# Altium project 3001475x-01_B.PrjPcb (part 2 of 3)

## Sheet 06 - Gigabit Ethernet, Mini PCIe, microSIM.SchDoc: Gigabit, Ethernet, Mini PCIe, MicroSIM
size A3; PageSetup: Record=PageOptions|CenterHorizontal=True|CenterVertical=True|PrintScale=0.70|XCorrection=1.00|YCorrection=1.00|PrintKind=0|BorderSize=5000000|LeftOffset=0|BottomOffset=0|Orientation=2|PaperLength=4200|PaperWidth=2970|Scale=100|PaperSource=7|PrintQuality=600|MediaType=1|DitherType=10|PaperKind=A4|PrintScaleMode=1; Author: Daniel Alesanco; SheetNumber: 6; SheetTotal: 13
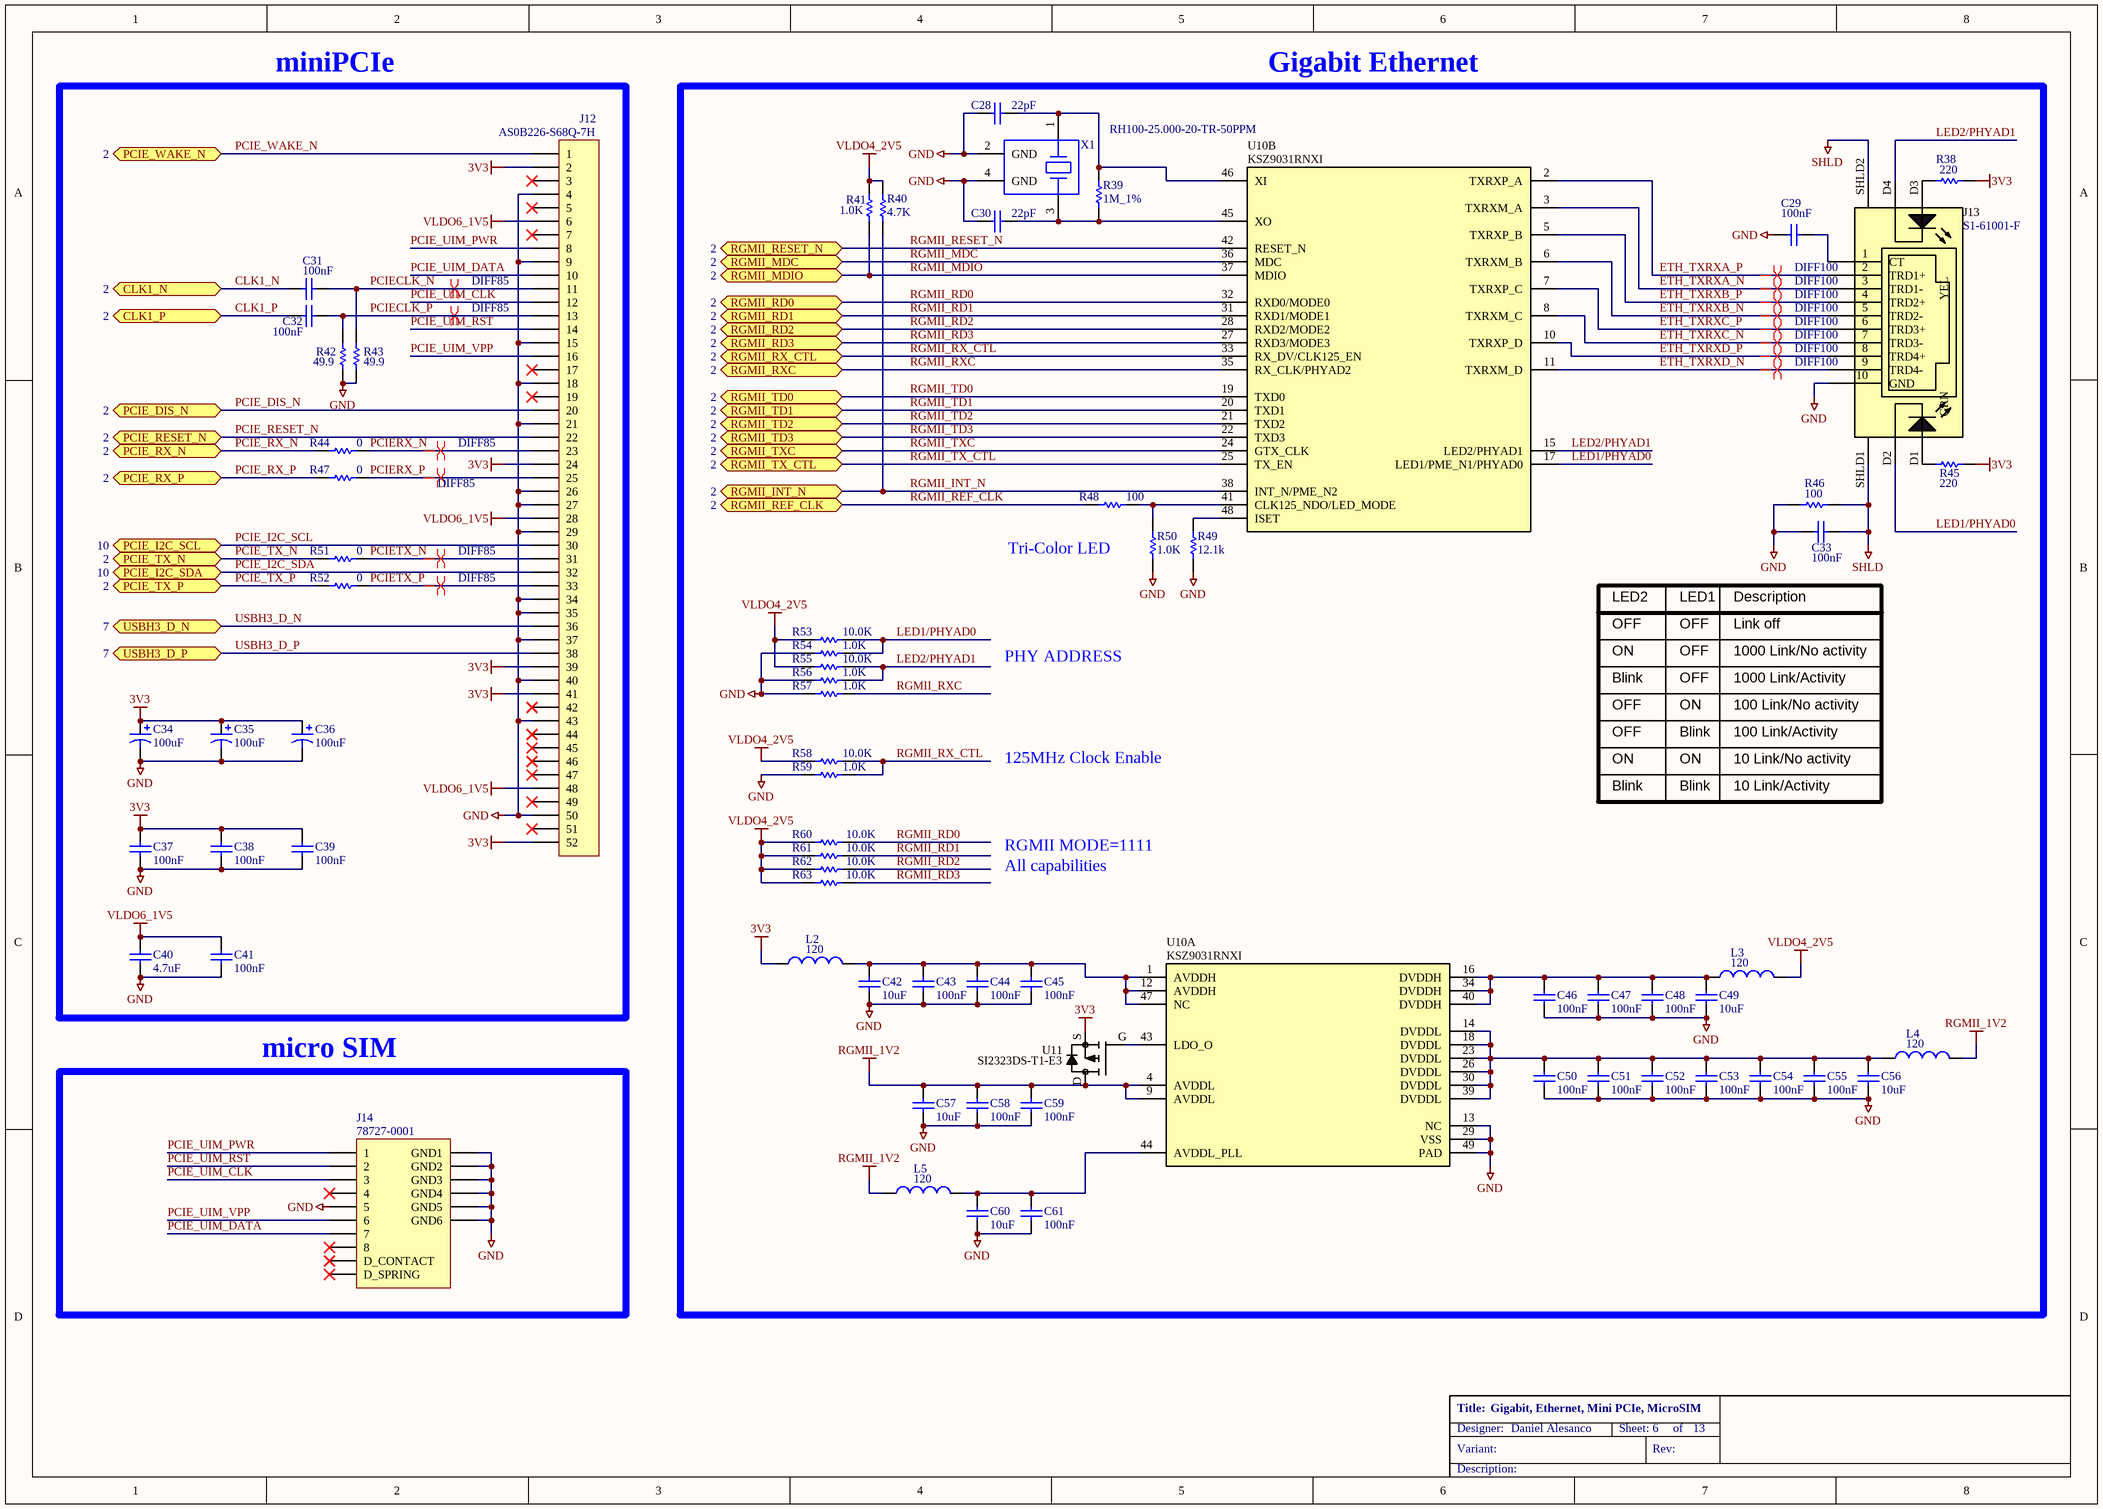
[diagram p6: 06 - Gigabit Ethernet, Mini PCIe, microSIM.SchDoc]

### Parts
C28  22pF  [CAPC1005X55N]
C29  100nF  [CAPC1005X55N]
C30  22pF  [CAPC1005X55N]
C31  100nF  [CAPC1005X55N]
C32  100nF  [CAPC1005X55N]
C33  100nF  [CAPC1005X55N]
C34  100uF  [CAPMP3216X120N]
C35  100uF  [CAPMP3216X120N]
C36  100uF  [CAPMP3216X120N]
C37  100nF  [CAPC1005X55N]
C38  100nF  [CAPC1005X55N]
C39  100nF  [CAPC1005X55N]
C40  4.7uF  [CAPC2013X135N]
C41  100nF  [CAPC1005X55N]
C42  10uF  [CAPC1005X55N]
C43  100nF  [CAPC1005X55N]
C44  100nF  [CAPC1005X55N]
C45  100nF  [CAPC1005X55N]
C46  100nF  [CAPC1005X55N]
C47  100nF  [CAPC1005X55N]
C48  100nF  [CAPC1005X55N]
C49  10uF  [CAPC1005X55N]
C50  100nF  [CAPC1005X55N]
C51  100nF  [CAPC1005X55N]
C52  100nF  [CAPC1005X55N]
C53  100nF  [CAPC1005X55N]
C54  100nF  [CAPC1005X55N]
C55  100nF  [CAPC1005X55N]
C56  10uF  [CAPC1005X55N]
C57  10uF  [CAPC1005X55N]
C58  100nF  [CAPC1005X55N]
C59  100nF  [CAPC1005X55N]
C60  10uF  [CAPC1005X55N]
C61  100nF  [CAPC1005X55N]
J12  Manufacturer_Part_Number: AS0B226-S68Q-7H  [FOXCONN_AS0B221-S68Q-7H]  (hidden comment: PCIe Minicard)
J13  Manufacturer_Part_Number: S1-61001-F  [BELFUSE_61001-F]  (hidden comment: RJ45)
J14  78727-0001  [MOLEX_78727-0001]
L2  120  [INDC1005X60N]
L3  120  [INDC1005X60N]
L4  120  [INDC1005X60N]
L5  120  [INDC1005X60N]
R38  220  [RESC1005X40N]
R39  1M_1%  [RESC1005X40N]
R40  4.7K  [RESC1005X40N]
R41  1.0K  [RESC1005X40N]
R42  49.9  [RESC1005X40N]
R43  49.9  [RESC1005X40N]
R44  0  [RESC1005X40N]
R45  220  [RESC1005X40N]
R46  100  [RESC1005X40N]
R47  0  [RESC1005X40N]
R48  100  [RESC1005X40N]
R49  12.1k  [RESC1005X40N]
R50  1.0K  [RESC1005X40N]
R51  0  [RESC1005X40N]
R52  0  [RESC1005X40N]
R53  10.0K  [RESC1005X40N]
R54  1.0K  [RESC1005X40N]
R55  10.0K  [RESC1005X40N]
R56  1.0K  [RESC1005X40N]
R57  1.0K  [RESC1005X40N]
R58  10.0K  [RESC1005X40N]
R59  1.0K  [RESC1005X40N]
R60  10.0K  [RESC1005X40N]
R61  10.0K  [RESC1005X40N]
R62  10.0K  [RESC1005X40N]
R63  10.0K  [RESC1005X40N]
U10  KSZ9031RNXI  [QFN50P700X700X100-49N]  (parts A,B of 2)
U11  SI2323DS-T1-E3  [SOT95P240X110_GSD-3N]
X1  RH100-25.000-20-TR-50PPM  [OSC210P320X250X90-4N]

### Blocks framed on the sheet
miniPCIe: C31 C32 C34-C41 J12 R42-R44 R47 R51 R52
Gigabit Ethernet: C28-C30 C33 C42-C61 J13 L2-L5 R38-R41 R45 R46 R48-R50 R53-R63 U10 U11 X1
micro SIM: J14

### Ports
CLK1_N (bidir, see 2), CLK1_P (bidir, see 2), PCIE_DIS_N (bidir, see 2), PCIE_I2C_SCL (bidir, see 10), PCIE_I2C_SDA (bidir, see 10), PCIE_RESET_N (bidir, see 2), PCIE_RX_N (bidir, see 2), PCIE_RX_P (bidir, see 2), PCIE_TX_N (bidir, see 2), PCIE_TX_P (bidir, see 2), PCIE_WAKE_N (bidir, see 2), RGMII_INT_N (bidir, see 2), RGMII_MDC (bidir, see 2), RGMII_MDIO (bidir, see 2), RGMII_RD0 (bidir, see 2), RGMII_RD1 (bidir, see 2), RGMII_RD2 (bidir, see 2), RGMII_RD3 (bidir, see 2), RGMII_REF_CLK (bidir, see 2), RGMII_RESET_N (bidir, see 2), RGMII_RX_CTL (bidir, see 2), RGMII_RXC (bidir, see 2), RGMII_TD0 (bidir, see 2), RGMII_TD1 (bidir, see 2), RGMII_TD2 (bidir, see 2), RGMII_TD3 (bidir, see 2), RGMII_TX_CTL (bidir, see 2), RGMII_TXC (bidir, see 2), USBH3_D_N (bidir, see 7), USBH3_D_P (bidir, see 7)

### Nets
3V3: C34.1 C35.1 C36.1 C37.2 C38.2 C39.2 J12.2 J12.24 J12.39 J12.41 J12.52 L2.1 R38.2 R45.2 U11.S
GND: C28.1 C29.1 C30.1 C33.2 C34.2 C35.2 C36.2 C37.1 C38.1 C39.1 C40.1 C41.1 C42.1 C43.1 C44.1 C45.1 C46.1 C47.1 C48.1 C49.1 C50.1 C51.1 C52.1 C53.1 C54.1 C55.1 C56.1 C57.1 C58.1 C59.1 C60.1 C61.1 J12.4 J12.9 J12.15 J12.18 J12.21 J12.26 J12.27 J12.29 J12.34 J12.35 J12.37 J12.40 J12.43 J12.50 J13.10(GND) J14.5 J14.11(GND1) J14.12(GND2) J14.13(GND3) J14.14(GND4) J14.15(GND5) J14.16(GND6) R42.1 R43.1 R46.1 R49.1 R50.1 R54.2 R56.2 R57.2 R59.2 U10.13(NC) U10.29(VSS) U10.49(PAD) X1.2(GND) X1.4(GND)
RGMII_1V2: C57.2 C58.2 C59.2 L4.2 L5.1 U10.4(AVDDL) U10.9(AVDDL) U11.D
SHLD: C33.1 J13.SHLD1(SHLD) J13.SHLD2(SHLD) R46.2
VLDO4_2V5: L3.2 R40.2 R41.2 R53.2 R55.2 R58.2 R60.2 R61.2 R62.2 R63.2
VLDO6_1V5: C40.2 C41.2 J12.6 J12.28 J12.48
CLK1_N: C31.1 ; port CLK1_N
CLK1_P: C32.1 ; port CLK1_P
ETH_TXRXA_N: J13.3(TRD1-) U10.3(TXRXM_A)
ETH_TXRXA_P: J13.2(TRD1+) U10.2(TXRXP_A)
ETH_TXRXB_N: J13.5(TRD2-) U10.6(TXRXM_B)
ETH_TXRXB_P: J13.4(TRD2+) U10.5(TXRXP_B)
ETH_TXRXC_N: J13.7(TRD3-) U10.8(TXRXM_C)
ETH_TXRXC_P: J13.6(TRD3+) U10.7(TXRXP_C)
ETH_TXRXD_N: J13.9(TRD4-) U10.11(TXRXM_D)
ETH_TXRXD_P: J13.8(TRD4+) U10.10(TXRXP_D)
LED1/PHYAD0: J13.D2 R53.1 R54.1 U10.17(LED1/PME_N1/PHYAD0)
LED2/PHYAD1: J13.D4 R55.1 R56.1 U10.15(LED2/PHYAD1)
PCIE_DIS_N: J12.20 ; port PCIE_DIS_N
PCIE_I2C_SCL: J12.30 ; port PCIE_I2C_SCL
PCIE_I2C_SDA: J12.32 ; port PCIE_I2C_SDA
PCIE_RESET_N: J12.22 ; port PCIE_RESET_N
PCIE_RX_N: R44.1 ; port PCIE_RX_N
PCIE_RX_P: R47.1 ; port PCIE_RX_P
PCIE_TX_N: R51.1 ; port PCIE_TX_N
PCIE_TX_P: R52.1 ; port PCIE_TX_P
PCIE_UIM_CLK: J12.12 J14.3
PCIE_UIM_DATA: J12.10 J14.7
PCIE_UIM_PWR: J12.8 J14.1
PCIE_UIM_RST: J12.14 J14.2
PCIE_UIM_VPP: J12.16 J14.6
PCIE_WAKE_N: J12.1 ; port PCIE_WAKE_N
PCIECLK_N: C31.2 J12.11 R43.2
PCIECLK_P: C32.2 J12.13 R42.2
PCIERX_N: J12.23 R44.2
PCIERX_P: J12.25 R47.2
PCIETX_N: J12.31 R51.2
PCIETX_P: J12.33 R52.2
RGMII_INT_N: R40.1 U10.38(INT_N/PME_N2) ; port RGMII_INT_N
RGMII_MDC: U10.36(MDC) ; port RGMII_MDC
RGMII_MDIO: R41.1 U10.37(MDIO) ; port RGMII_MDIO
RGMII_RD0: R60.1 U10.32(RXD0/MODE0) ; port RGMII_RD0
RGMII_RD1: R61.1 U10.31(RXD1/MODE1) ; port RGMII_RD1
RGMII_RD2: R62.1 U10.28(RXD2/MODE2) ; port RGMII_RD2
RGMII_RD3: R63.1 U10.27(RXD3/MODE3) ; port RGMII_RD3
RGMII_REF_CLK: R48.1 ; port RGMII_REF_CLK
RGMII_RESET_N: U10.42(RESET_N) ; port RGMII_RESET_N
RGMII_RX_CTL: R58.1 R59.1 U10.33(RX_DV/CLK125_EN) ; port RGMII_RX_CTL
RGMII_RXC: R57.1 U10.35(RX_CLK/PHYAD2) ; port RGMII_RXC
RGMII_TD0: U10.19(TXD0) ; port RGMII_TD0
RGMII_TD1: U10.20(TXD1) ; port RGMII_TD1
RGMII_TD2: U10.21(TXD2) ; port RGMII_TD2
RGMII_TD3: U10.22(TXD3) ; port RGMII_TD3
RGMII_TX_CTL: U10.25(TX_EN) ; port RGMII_TX_CTL
RGMII_TXC: U10.24(GTX_CLK) ; port RGMII_TXC
USBH3_D_N: J12.36 ; port USBH3_D_N
USBH3_D_P: J12.38 ; port USBH3_D_P
NetC28_2: C28.2 R39.2 U10.46(XI) X1.1
NetC29_2: C29.2 J13.1(CT)
NetC30_2: C30.2 R39.1 U10.45(XO) X1.3
NetC42_2: C42.2 C43.2 C44.2 C45.2 L2.2 U10.1(AVDDH) U10.12(AVDDH) U10.47(NC)
NetC46_2: C46.2 C47.2 C48.2 C49.2 L3.1 U10.16(DVDDH) U10.34(DVDDH) U10.40(DVDDH)
NetC50_2: C50.2 C51.2 C52.2 C53.2 C54.2 C55.2 C56.2 L4.1 U10.14(DVDDL) U10.18(DVDDL) U10.23(DVDDL) U10.26(DVDDL) U10.30(DVDDL) U10.39(DVDDL)
NetC60_2: C60.2 C61.2 L5.2 U10.44(AVDDL_PLL)
NetJ13_D1: J13.D1 R45.1
NetJ13_D3: J13.D3 R38.1
NetR48_2: R48.2 R50.2 U10.41(CLK125_NDO/LED_MODE)
NetR49_2: R49.2 U10.48(ISET)
NetU10_43: U10.43(LDO_O) U11.G

Not connected (* = marked no-connect by the designer): J12 3* 5* 7* 17* 19* 42* 44* 45* 46* 47* 49* 51*; J14 4* 8* 9(D_CONTACT)* 10(D_SPRING)*

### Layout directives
differential pair; net class DIFF100: ETH_TXRXA_N, ETH_TXRXA_P, ETH_TXRXB_N, ETH_TXRXB_P, ETH_TXRXC_N, ETH_TXRXC_P, ETH_TXRXD_N, ETH_TXRXD_P
differential pair; net class DIFF85: PCIECLK_N, PCIECLK_P, PCIERX_N, PCIERX_P, PCIETX_N, PCIETX_P

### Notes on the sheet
- Tri-Color LED
- LED2
- OFF
- LED1
- Description
- Link off
- PHY ADDRESS
- ON
- Blink
- 1000 Link/No activity
- 1000 Link/Activity
- 100 Link/No activity
- 125MHz Clock Enable
- 100 Link/Activity
- 10 Link/No activity
- RGMII MODE=1111
- 10 Link/Activity
- All capabilities

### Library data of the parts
C28 C30 = 1001166: CAP CER 22PF 50V 5% NP0 0402; Part_Type: Capacitor; Manufacturer: Murata; Manufacturer_Part_Number: GRM1555C1H220JA01D; Digi_PN: 14050367; Component_Life_Cycle_State: Reviewed; Area: 0.95; Project: CCWMX6_SBC board; Voltage: 50; Temp_Coef: C0G, NP0
C29 C31-C33 C37-C39 C41 C43-C48 C50-C55 C58 C59 C61 = 1000006: CAP 100nF 16V 10% X7R 0402; Part_Type: Capacitor; Manufacturer: Murata; Manufacturer_Part_Number: GRM155R71C104KA88D; Component_Life_Cycle_State: CAD Reviewed; Area: 0.95; Project: KITT; Tolerance: 10; Digi_PN: 14050552
C34-C36 = 1001196: CAP TANT 100UF 6.3V 20% 1206; Part_Type: Capacitor; Manufacturer: Rohm; Manufacturer_Part_Number: TCTAL0J107M8R; Digi_PN: 14050490; Component_Life_Cycle_State: Reviewed; Area: 8.01; Project: CCWMX6_SBC board; Voltage: 6.3
C40 = 1000500: CAP CER 4.7UF 25V 10% X5R 0805; Part_Type: Capacitor; Manufacturer: Murata; Manufacturer_Part_Number: GRM21BR61E475KA12L; Component_Life_Cycle_State: Reviewed; Area: 4.24; Project: SDR Prototype RF Board; Voltage: 25; Digi_PN: 14050307
C42 C49 C56 C57 C60 = 1001168: CAP CER 10UF 10V 20% X5R 0402; Part_Type: Capacitor; Manufacturer: Samsung; Manufacturer_Part_Number: CL05A106MP5NUNC; Digi_PN: 14050689; Component_Life_Cycle_State: Reviewed; Area: 0.95; Project: CCWMX6_SBC board; Voltage: 10
J12 = 1001130: SMCONN,MINI PCI EXP, 6.8MM HT; Part_Type: Connector; Manufacturer: Foxconn; Digi_PN: 18000349; Component_Life_Cycle_State: Reviewed; Area: 150; Project: CCWMX6_SBC board
J13 = 1001142: CONN MAGJACK 1PORT 1000 BASE-T; Part_Type: Connector; Manufacturer: Bel Fuse; Digi_PN: 18000677; Component_Life_Cycle_State: Reviewed; Area: 348.2467; Project: CCWMX6_SBC board
J14 = 1001120: MEMORY CARD 6POS PUSH/PULL SMD; Part_Type: Connector; Manufacturer: Molex; Digi_PN: 18000638; Component_Life_Cycle_State: Reviewed; Area: 217; Project: CCWMX6_SBC board
L2-L5 = 1001175: FERRITE BEAD 120 OHM .35A 0402; Part_Type: Filter; Manufacturer: Wurth Electronics Inc; Manufacturer_Part_Number: 7427927112; Digi_PN: 21000128; Component_Life_Cycle_State: Reviewed; Area: 1.12; Project: CCWMX6_SBC board
R38 R45 = 1001154: RES 220 OHM 1/16W 1% 0402 SMD; Part_Type: Resistor; Manufacturer: Yageo; Manufacturer_Part_Number: RC0402FR-07220RL; Digi_PN: 13050623; Component_Life_Cycle_State: Reviewed; Area: 0.95; Project: CCWMX6_SBC board
R39 = 1000971: RES 1.00M OHM 1/16W 1% 0402 SMD; Part_Type: Resistor; Manufacturer: Yageo; Manufacturer_Part_Number: RC0402FR-071ML; Digi_PN: 13050561; Component_Life_Cycle_State: Reviewed; Area: 0.95; Project: ConnectCore i.MX6 module; Power_WV_SRF: 63; Tolerance: 1
R40 = 1000038: RES 4.7K OHM 1/10W 5% 0402 SMD; Part_Type: Resistor; Manufacturer: Panasonic - ECG; Manufacturer_Part_Number: ERJ-2GEJ472X; Component_Life_Cycle_State: Proven; Area: 0.95; Project: Adjustable Foundation; Power_WV_SRF: 100; Tolerance: 5; Digi_PN: 13050549
R41 R50 R54 R56 R57 R59 = 1000079: RES 1.00K OHM 1/10W 1% 0402 SMD; Part_Type: Resistor; Manufacturer: Panasonic - ECG; Manufacturer_Part_Number: ERJ-2RKF1001X; Digi_PN: 13050636; Component_Life_Cycle_State: Proven; Area: 0.95; Project: Adjustable Foundation; Power_WV_SRF: 10
R42 R43 = 1000466: RES 49.9 OHM 1/10W 1% 0402 SMD; Part_Type: Resistor; Manufacturer: Panasonic - ECG; Manufacturer_Part_Number: ERJ-2RKF49R9X; Component_Life_Cycle_State: CAD Reviewed; Area: 0.95; Project: KITT; Power_WV_SRF: 100; Digi_PN: 13050665
R44 R47 R51 R52 = 1000076: RES 0.0 OHM 1/10W 0402 SMD; Part_Type: Resistor; Manufacturer: Panasonic - ECG; Manufacturer_Part_Number: ERJ-2GE0R00X; Component_Life_Cycle_State: Proven; Area: 0.95; Project: Adjustable Foundation; Power_WV_SRF: 10; Digi_PN: 13050387
R46 R48 = 1000467: RES 100 OHM 1/10W 1% 0402 SMD; Part_Type: Resistor; Manufacturer: Panasonic - ECG; Manufacturer_Part_Number: ERJ-2RKF1000X; Component_Life_Cycle_State: CAD Reviewed; Area: 0.95; Project: KITT; Digi_PN: 13050626
R49 = 1000828: RES 12.1K OHM 1/10W 1% 0402 SMD; Part_Type: Resistor; Manufacturer: Panasonic - ECG; Manufacturer_Part_Number: ERJ-2RKF1212X; Component_Life_Cycle_State: Reviewed; Area: 0.95; Project: SmartMeter2; Power_WV_SRF: 100; Digi_PN: 13050496
R53 R55 R58 R60-R63 = 1000537: RES 10.0K OHM 1/10W 1% 0402 SMD; Part_Type: Resistor; Manufacturer: Panasonic - ECG; Manufacturer_Part_Number: ERJ-2RKF1002X; Component_Life_Cycle_State: CAD Reviewed; Area: 0.95; Project: KITT; Power_WV_SRF: 100; Digi_PN: 13050644
U10 = 1001110: IC TXRX ETHERNET 48-QFN; Manufacturer: Micrel; Digi_PN: 16051862; Component_Life_Cycle_State: Reviewed; Area: 49; Project: CCWMX6_SBC board
U11 = 1001163: MOSFET P-CH 20V 3.7A SOT23-3; Part_Type: IC; Manufacturer: Vishay Siliconix; Digi_PN: 17050358; Component_Life_Cycle_State: Reviewed; Area: 10.92; Project: CCWMX6_SBC board
X1 = 1001176: CRYSTAL 25MHz SMT; Part_Type: Crystals-Oscillators; Manufacturer: Raltron; Digi_PN: 20000127; Component_Life_Cycle_State: Reviewed; Area: 3.2; Project: CCWMX6_SBC board

## Sheet 07 - USB OTG, USB HUB, USB Host.SchDoc: USB OTG, USB Hub, USB Host
size A3; PageSetup: Record=PageOptions|CenterHorizontal=True|CenterVertical=True|PrintScale=0.70|XCorrection=1.00|YCorrection=1.00|PrintKind=0|BorderSize=5000000|LeftOffset=0|BottomOffset=0|Orientation=2|PaperLength=4200|PaperWidth=2970|Scale=100|PaperSource=7|PrintQuality=600|MediaType=1|DitherType=10|PaperKind=A4|PrintScaleMode=1; Author: Daniel Alesanco; SheetNumber: 7; SheetTotal: 13
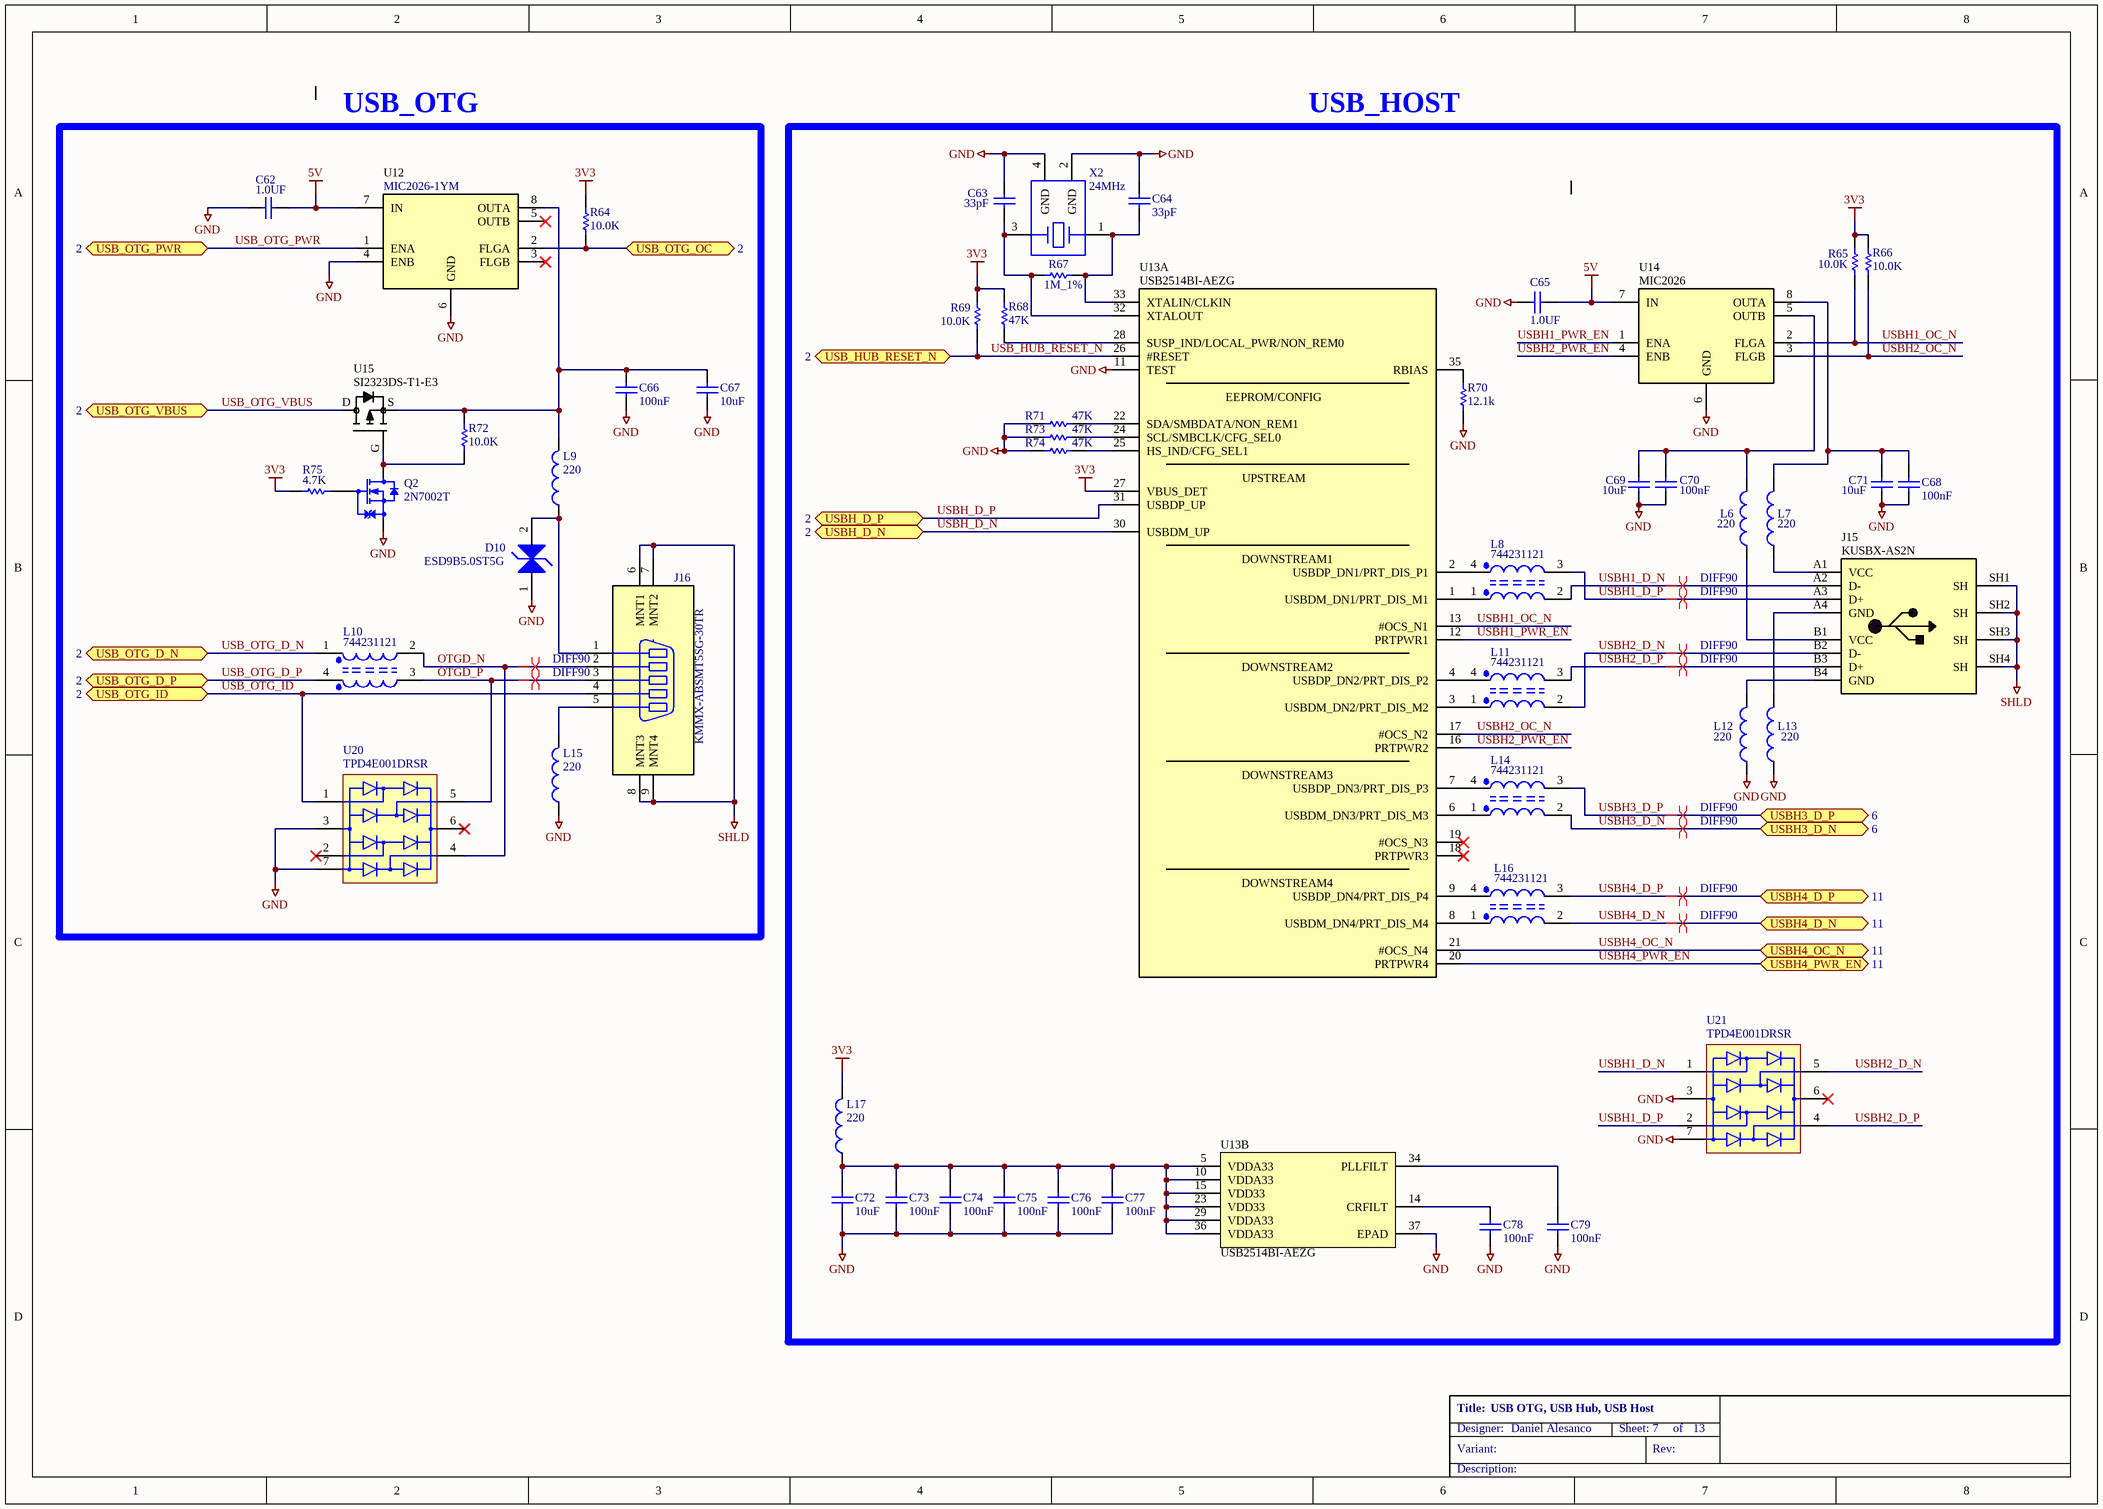
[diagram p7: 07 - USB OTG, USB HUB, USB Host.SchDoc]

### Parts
C62  1.0UF  [CAPC1005X55N]
C63  33pF  [CAPC1005X55N]
C64  33pF  [CAPC1005X55N]
C65  1.0UF  [CAPC1005X55N]
C66  100nF  [CAPC1005X55N]
C67  10uF  [CAPC1005X55N]
C68  100nF  [CAPC1005X55N]
C69  10uF  [CAPC1005X55N]
C70  100nF  [CAPC1005X55N]
C71  10uF  [CAPC1005X55N]
C72  10uF  [CAPC1005X55N]
C73  100nF  [CAPC1005X55N]
C74  100nF  [CAPC1005X55N]
C75  100nF  [CAPC1005X55N]
C76  100nF  [CAPC1005X55N]
C77  100nF  [CAPC1005X55N]
C78  100nF  [CAPC1005X55N]
C79  100nF  [CAPC1005X55N]
D10  ESD9B5.0ST5G  [SODFL1006X43N12]
J15  KUSBX-AS2N  [KYCON_KUSBX-AS2N]
J16  KMMX-ABSMT5SG-30TR  [KYCON_KMMX-ABSMT5]
L6  220  [INDC2013X110N]
L7  220  [INDC2013X110N]
L8  744231121  [FIL_DLW21H]
L9  220  [INDC2013X110N]
L10  744231121  [FIL_DLW21H]
L11  744231121  [FIL_DLW21H]
L12  220  [INDC2013X110N]
L13  220  [INDC2013X110N]
L14  744231121  [FIL_DLW21H]
L15  220  [INDC2013X110N]
L16  744231121  [FIL_DLW21H]
L17  220  [INDC2013X110N]
Q2  2N7002T  [SOTFL50P160X80_GSD-3N]
R64  10.0K  [RESC1005X40N]
R65  10.0K  [RESC1005X40N]
R66  10.0K  [RESC1005X40N]
R67  1M_1%  [RESC1005X40N]
R68  47K  [RESC1005X40N]
R69  10.0K  [RESC1005X40N]
R70  12.1k  [RESC1005X40N]
R71  47K  [RESC1005X40N]
R72  10.0K  [RESC1005X40N]
R73  47K  [RESC1005X40N]
R74  47K  [RESC1005X40N]
R75  4.7K  [RESC1005X40N]
U12  Manufacturer_Part_Number: MIC2026-1YM  [SOIC127P600X175-8N]  (hidden comment: MIC2026)
U13  USB2514BI-AEZG  [QFN50P600X600X100-37AN]  (parts A,B of 2)
U14  MIC2026  [SOIC127P600X175-8N]
U15  SI2323DS-T1-E3  [SOT95P240X110_GSD-3N]
U20  TPD4E001DRSR  [SON95P300X300X80-7N]
U21  TPD4E001DRSR  [SON95P300X300X80-7N]
X2  24MHz  [XTAL_C3E-3427]

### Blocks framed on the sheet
USB_OTG: C62 C66 C67 D10 J16 L9 L10 L15 Q2 R64 R72 R75 U12 U15 U20
USB_HOST: C63-C65 C68-C79 J15 L6-L8 L11-L14 L16 L17 R65-R71 R73 R74 U13 U14 U21 X2

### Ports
USB_HUB_RESET_N (bidir, see 2), USB_OTG_D_N (bidir, see 2), USB_OTG_D_P (bidir, see 2), USB_OTG_ID (bidir, see 2), USB_OTG_OC (bidir, see 2), USB_OTG_PWR (bidir, see 2), USB_OTG_VBUS (bidir, see 2), USBH3_D_N (bidir, see 6), USBH3_D_P (bidir, see 6), USBH4_D_N (bidir, see 11), USBH4_D_P (bidir, see 11), USBH4_OC_N (bidir, see 11), USBH4_PWR_EN (bidir, see 11), USBH_D_N (bidir, see 2), USBH_D_P (bidir, see 2)

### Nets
3V3: L17.2 R64.2 R65.2 R66.2 R68.2 R69.1 R75.1 U13.27(VBUS_DET)
5V: C62.2 C65.1 U12.7(IN) U14.7(IN)
GND: C62.1 C63.2 C64.2 C65.2 C66.1 C67.1 C68.1 C69.1 C70.1 C71.1 C72.1 C73.1 C74.1 C75.1 C76.1 C77.1 C78.1 C79.1 D10.1 L12.1 L13.1 L15.1 Q2.S R70.1 R71.1 R73.1 R74.1 U12.4(ENB) U12.6(GND) U13.11(TEST) U13.37(EPAD) U14.6(GND) U20.3(GND) U20.7(GND) U21.3(GND) U21.7(GND) X2.2(GND) X2.4(GND)
SHLD: J15.SH1(SH) J15.SH2(SH) J15.SH3(SH) J15.SH4(SH) J16.6(MNT1) J16.7(MNT2) J16.8(MNT3) J16.9(MNT4)
OTGD_N: J16.2 L10.2 U20.4(I/O)
OTGD_P: J16.3 L10.3 U20.5(I/O)
USB_HUB_RESET_N: R69.2 U13.26(#RESET) ; port USB_HUB_RESET_N
USB_OTG_D_N: L10.1 ; port USB_OTG_D_N
USB_OTG_D_P: L10.4 ; port USB_OTG_D_P
USB_OTG_ID: J16.4 U20.1(I/O) ; port USB_OTG_ID
USB_OTG_OC: R64.1 U12.2(FLGA) ; port USB_OTG_OC
USB_OTG_PWR: U12.1(ENA) ; port USB_OTG_PWR
USB_OTG_VBUS: U15.D ; port USB_OTG_VBUS
USBH1_D_N: J15.A2(D-) L8.2 U21.1(I/O)
USBH1_D_P: J15.A3(D+) L8.3 U21.2(I/O)
USBH1_OC_N: R65.1 U13.13(#OCS_N1) U14.2(FLGA)
USBH1_PWR_EN: U13.12(PRTPWR1) U14.1(ENA)
USBH2_D_N: J15.B2(D-) L11.2 U21.5(I/O)
USBH2_D_P: J15.B3(D+) L11.3 U21.4(I/O)
USBH2_OC_N: R66.1 U13.17(#OCS_N2) U14.3(FLGB)
USBH2_PWR_EN: U13.16(PRTPWR2) U14.4(ENB)
USBH3_D_N: L14.2 ; port USBH3_D_N
USBH3_D_P: L14.3 ; port USBH3_D_P
USBH4_D_N: L16.2 ; port USBH4_D_N
USBH4_D_P: L16.3 ; port USBH4_D_P
USBH4_OC_N: U13.21(#OCS_N4) ; port USBH4_OC_N
USBH4_PWR_EN: U13.20(PRTPWR4) ; port USBH4_PWR_EN
USBH_D_N: U13.30(USBDM_UP) ; port USBH_D_N
USBH_D_P: U13.31(USBDP_UP) ; port USBH_D_P
NetC63_1: C63.1 R67.1 U13.32(XTALOUT) X2.3
NetC64_1: C64.1 R67.2 U13.33(XTALIN/CLKIN) X2.1
NetC66_2: C66.2 C67.2 L9.2 R72.1 U12.8(OUTA) U15.S
NetC68_2: C68.2 C71.2 L7.2 U14.8(OUTA)
NetC69_2: C69.2 C70.2 L6.2 U14.5(OUTB)
NetC72_2: C72.2 C73.2 C74.2 C75.2 C76.2 C77.2 L17.1 U13.5(VDDA33) U13.10(VDDA33) U13.15(VDD33) U13.23(VDD33) U13.29(VDDA33) U13.36(VDDA33)
NetC78_2: C78.2 U13.14(CRFILT)
NetC79_2: C79.2 U13.34(PLLFILT)
NetD10_2: D10.2 J16.1 L9.1
NetJ15_A1: J15.A1(VCC) L7.1
NetJ15_A4: J15.A4(GND) L13.2
NetJ15_B1: J15.B1(VCC) L6.1
NetJ15_B4: J15.B4(GND) L12.2
NetJ16_5: J16.5 L15.2
NetL8_1: L8.1 U13.1(USBDM_DN1/PRT_DIS_M1)
NetL8_4: L8.4 U13.2(USBDP_DN1/PRT_DIS_P1)
NetL11_1: L11.1 U13.3(USBDM_DN2/PRT_DIS_M2)
NetL11_4: L11.4 U13.4(USBDP_DN2/PRT_DIS_P2)
NetL14_1: L14.1 U13.6(USBDM_DN3/PRT_DIS_M3)
NetL14_4: L14.4 U13.7(USBDP_DN3/PRT_DIS_P3)
NetL16_1: L16.1 U13.8(USBDM_DN4/PRT_DIS_M4)
NetL16_4: L16.4 U13.9(USBDP_DN4/PRT_DIS_P4)
NetQ2_D: Q2.D R72.2 U15.G
NetQ2_G: Q2.G R75.2
NetR68_1: R68.1 U13.28(SUSP_IND/LOCAL_PWR/NON_REM0)
NetR70_2: R70.2 U13.35(RBIAS)
NetR71_2: R71.2 U13.22(SDA/SMBDATA/NON_REM1)
NetR73_2: R73.2 U13.24(SCL/SMBCLK/CFG_SEL0)
NetR74_2: R74.2 U13.25(HS_IND/CFG_SEL1)

Not connected (* = marked no-connect by the designer): U12 3(FLGB)* 5(OUTB)*; U13 18(PRTPWR3)* 19(#OCS_N3)*; U20 2(I/O)* 6(VCC)*; U21 6(VCC)*

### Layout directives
differential pair; net class DIFF90: OTGD_N, OTGD_P, USBH1_D_N, USBH1_D_P, USBH2_D_N, USBH2_D_P, USBH3_D_N, USBH3_D_P, USBH4_D_N, USBH4_D_P

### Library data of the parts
C62 C65 = 1001167: CAP CER 1UF 10V 10% X5R 0402; Part_Type: Capacitor; Manufacturer: Murata; Manufacturer_Part_Number: GRM155R61A105KE15D; Digi_PN: 14050399; Component_Life_Cycle_State: Reviewed; Area: 0.95; Project: CCWMX6_SBC board; Voltage: 10
C63 C64 = 1000010: CAP 33pF 50V 5% NP0 0402; Part_Type: Capacitor; Manufacturer: Murata; Manufacturer_Part_Number: GRM1555C1H330JA01D; Component_Life_Cycle_State: Proven; Area: 0.95; Project: USB UART to USB Transceiver; Voltage: 50; Tolerance: 5; Digi_PN: 14050400
C66 C68 C70 C73-C79 = 1000006: as C29 on sheet 06 - Gigabit Ethernet, Mini PCIe, microSIM
C67 C69 C71 C72 = 1001168: as C42 on sheet 06 - Gigabit Ethernet, Mini PCIe, microSIM
D10 = 1001264: TVS DIODE 5VWM SOD923; Part_Type: Diodes; Manufacturer: On Semiconductor; Digi_PN: 17050587; Component_Life_Cycle_State: Reviewed; Area: 1.5; Project: CCWMX6_SBC board
J15 = 1001121: USB Stacked Dual A type; Part_Type: Connector; Manufacturer: KYCON; Digi_PN: 18000276; Component_Life_Cycle_State: Reviewed; Area: 164; Project: CCWMX6_SBC board
J16 = 1001117: CONN RECEPT MICRO-USB TYPE AB R/A; Part_Type: Connector; Manufacturer: KYCON; Digi_PN: 18000401; Component_Life_Cycle_State: Reviewed; Area: 40; Project: CCWMX6_SBC board
L6 L7 L9 L12 L13 L15 L17 = 1001174: FERRITE BEAD 220 OHM 2.0A 0805; Manufacturer: Wurth Electronics Inc; Manufacturer_Part_Number: 742792022; Digi_PN: 21000146; Component_Life_Cycle_State: Reviewed; Area: 4.24; Project: CCWMX6_SBC board
L8 L10 L11 L14 L16 = 1001173: CHOKE COM MODE 120 OHM .37A; Part_Type: Inductor; Manufacturer: Wurth Electronics Inc; Digi_PN: 21000143; Component_Life_Cycle_State: Reviewed; Area: 2.4; Project: CCWMX6_SBC board
Q2 = 1000715: MOSFET N-CH 60V 115MA SOT-523F; Part_Type: Transistor; Manufacturer: Fairchild Semiconductor; Digi_PN: 17050797; Component_Life_Cycle_State: CAD Reviewed; Area: 3.06; Project: SmartMeter2
R64-R66 R69 R72 = 1000537: as R53 on sheet 06 - Gigabit Ethernet, Mini PCIe, microSIM
R67 = 1000971: as R39 on sheet 06 - Gigabit Ethernet, Mini PCIe, microSIM
R68 R71 R73 R74 = 1001155: RES 47.0K OHM 1/16W 1% 0402 SMD; Part_Type: Resistor; Manufacturer: Vishay Dale; Manufacturer_Part_Number: CRCW040247K0FKED; Digi_PN: 13050646; Component_Life_Cycle_State: Reviewed; Area: 0.95; Project: CCWMX6_SBC board
R70 = 1000828: as R49 on sheet 06 - Gigabit Ethernet, Mini PCIe, microSIM
R75 = 1000038: as R40 on sheet 06 - Gigabit Ethernet, Mini PCIe, microSIM
U12 = 1001143: IC SW DISTRIBUTION 2CHAN 8SOIC; Manufacturer: Micrel; Digi_PN: 16051879; Component_Life_Cycle_State: Reviewed; Area: 29.58; Project: CCWMX6_SBC board
U13 = 1001114: 4-PORT USB 2.0 HUB CTRLR 36VQFN; Part_Type: IC; Manufacturer: SMSC; Digi_PN: 16051280; Component_Life_Cycle_State: Reviewed; Area: 36; Project: CCWMX6_SBC board
U14 = 1001143: IC SW DISTRIBUTION 2CHAN 8SOIC; Manufacturer: Micrel; Manufacturer_Part_Number: MIC2026-1YM; Digi_PN: 16051879; Component_Life_Cycle_State: Reviewed; Area: 29.58; Project: CCWMX6_SBC board
U15 = 1001163: as U11 on sheet 06 - Gigabit Ethernet, Mini PCIe, microSIM
U20 U21 = 1001265: TVS DIODE 5.5VWM 6SON; Part_Type: IC; Manufacturer: Texas Instruments; Digi_PN: 17050690; Component_Life_Cycle_State: Reviewed; Area: 10; Project: CCWMX6_SBC board
X2 = 1001134: CRYSTAL 24MHZ 18PF SMD; Part_Type: Crystals-Oscillators; Manufacturer: Aker; Manufacturer_Part_Number: C3E-24.000-18-3030-X-R; Digi_PN: 20000223; Component_Life_Cycle_State: Reviewed; Area: 9.18; Project: CCWMX6_SBC board

## Sheet 08 - Displays, HDMI, Cameras.SchDoc: Displays, HDMI, Cameras
size A3; PageSetup: Record=PageOptions|CenterHorizontal=True|CenterVertical=True|PrintScale=0.70|XCorrection=1.00|YCorrection=1.00|PrintKind=0|BorderSize=5000000|LeftOffset=0|BottomOffset=0|Orientation=2|PaperLength=4200|PaperWidth=2970|Scale=100|PaperSource=7|PrintQuality=600|MediaType=1|DitherType=10|PaperKind=A4|PrintScaleMode=1; Author: Daniel Alesanco; SheetNumber: 8; SheetTotal: 13
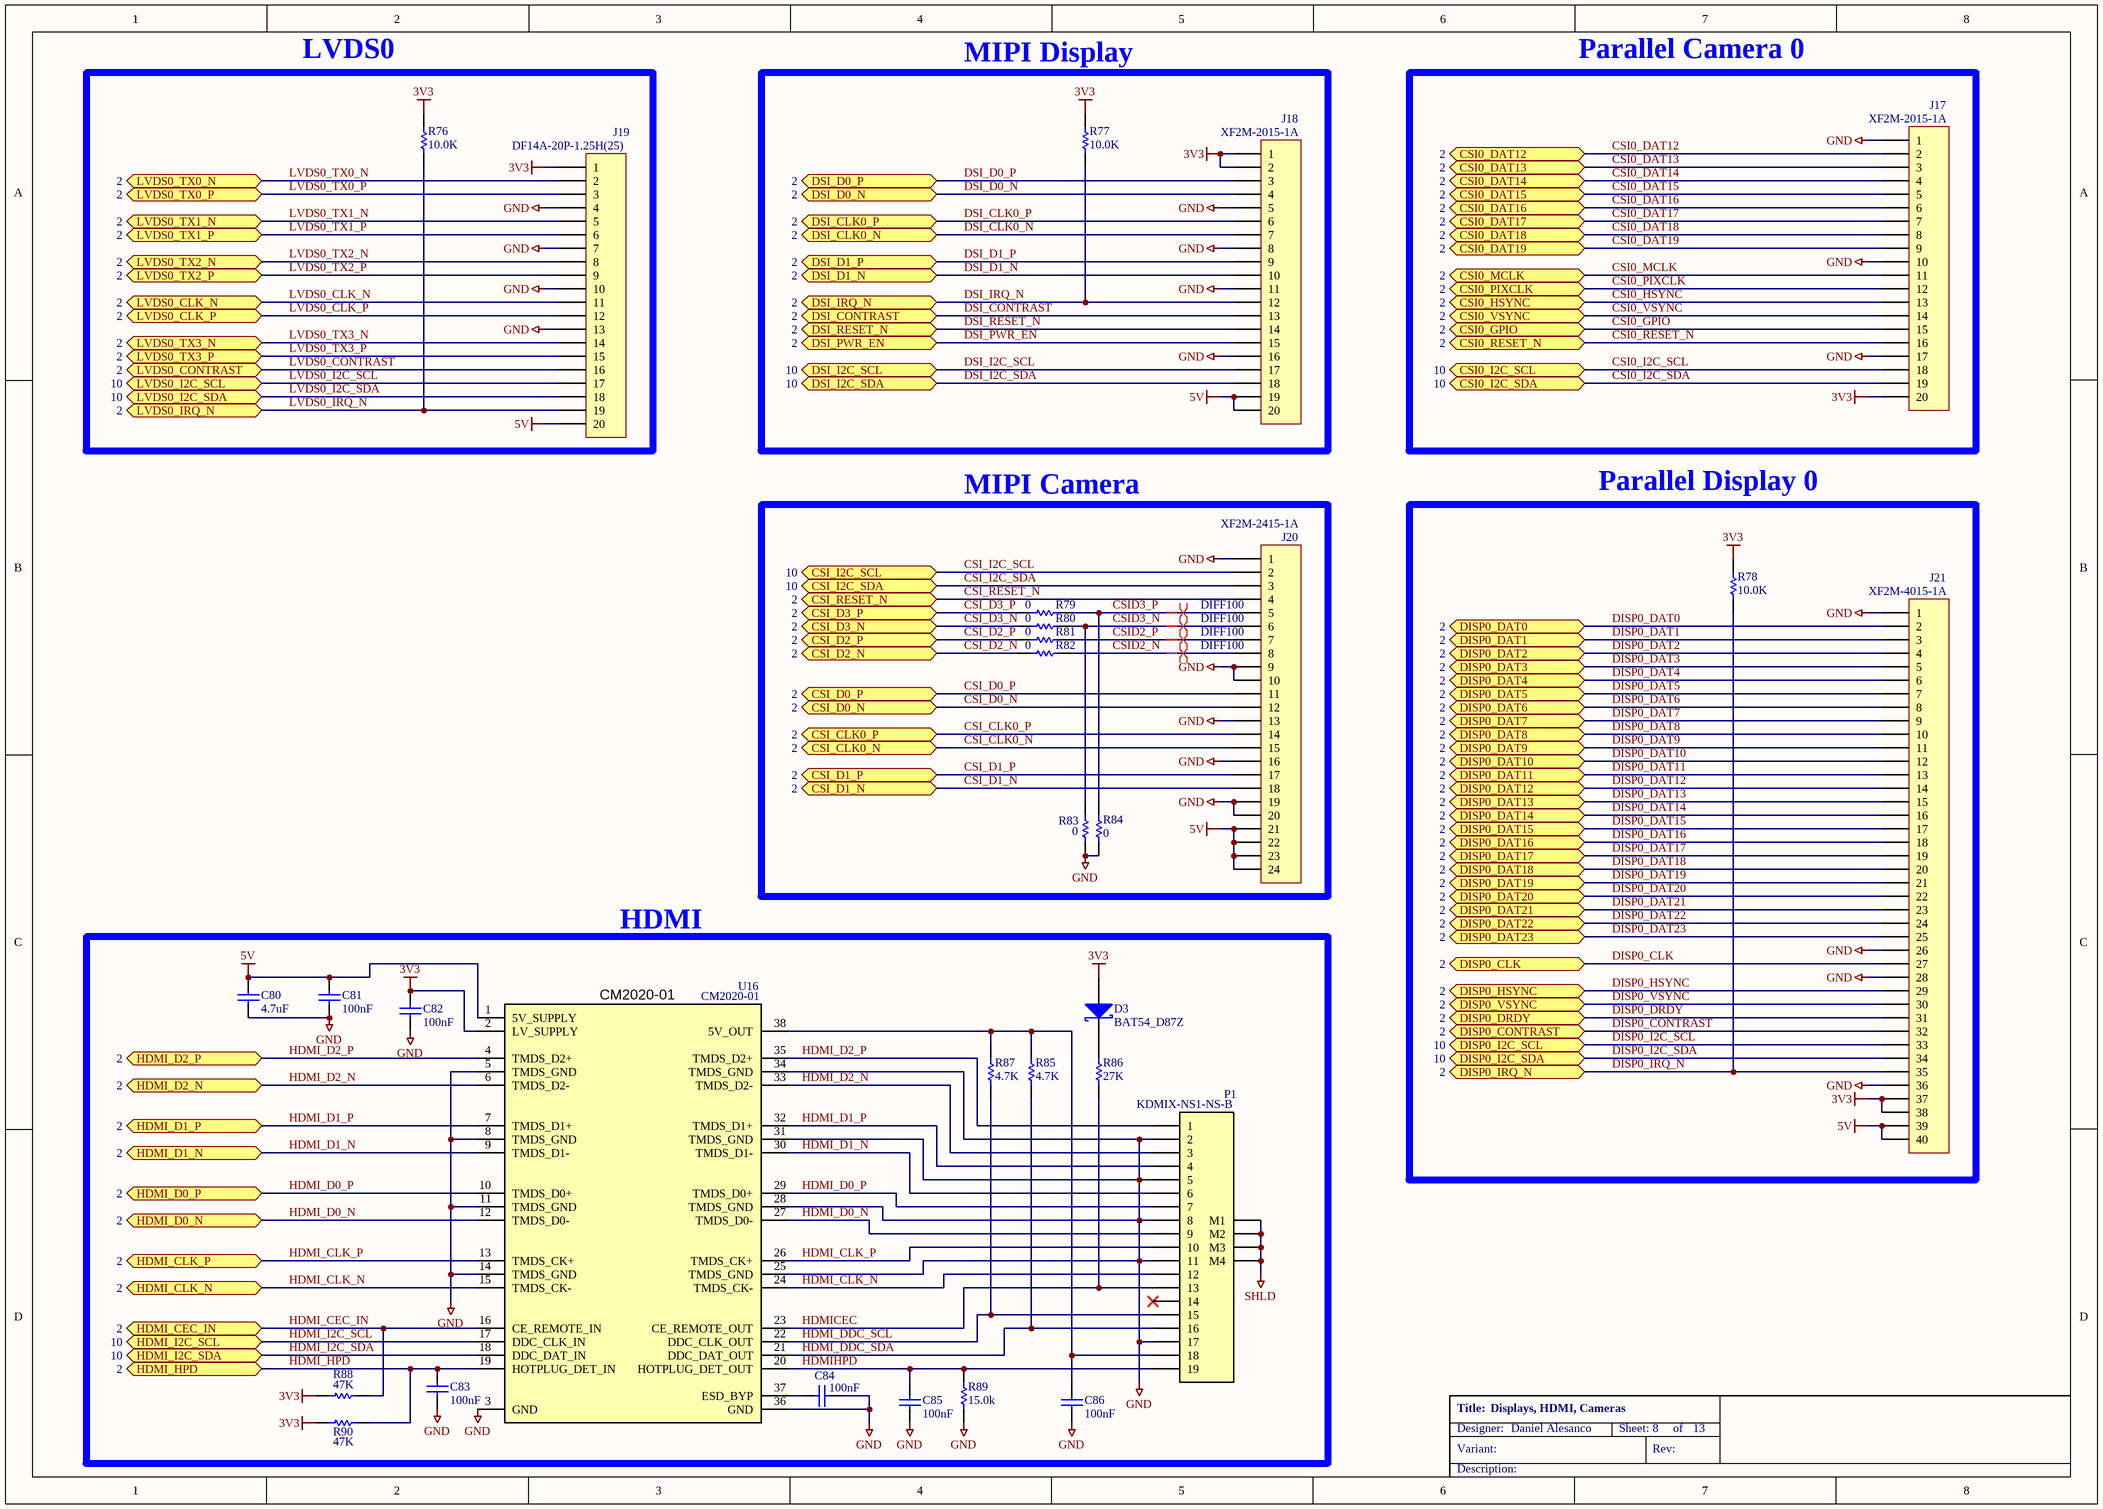
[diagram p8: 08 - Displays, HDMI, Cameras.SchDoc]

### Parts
C80  4.7uF  [CAPC2013X135N]
C81  100nF  [CAPC1005X55N]
C82  100nF  [CAPC1005X55N]
C83  100nF  [CAPC1005X55N]
C84  100nF  [CAPC1005X55N]
C85  100nF  [CAPC1005X55N]
C86  100nF  [CAPC1005X55N]
D3  BAT54_D87Z  [SOT95P240X110_AXK-3N]
J17  Manufacturer_Part_Number: XF2M-2015-1A  [omron_xf2m-2015-1a]  (hidden comment: 1x20P)
J18  Manufacturer_Part_Number: XF2M-2015-1A  [omron_xf2m-2015-1a]  (hidden comment: 1x20P)
J19  DF14A-20P-1.25H(25)  [HIROSE_DF14A-20P-1.25H]
J20  Manufacturer_Part_Number: XF2M-2415-1A  [OMRON_XF2M-2415-1A]  (hidden comment: 1x24P)
J21  Manufacturer_Part_Number: XF2M-4015-1A  [OMRON_XF2M-4015-1A]  (hidden comment: 1x40)
P1  KDMIX-NS1-NS-B  [KYCON_KDMIX]
R76  10.0K  [RESC1005X40N]
R77  10.0K  [RESC1005X40N]
R78  10.0K  [RESC1005X40N]
R79  0  [RESC1005X40N]
R80  0  [RESC1005X40N]
R81  0  [RESC1005X40N]
R82  0  [RESC1005X40N]
R83  0  [RESC1005X40N]
R84  0  [RESC1005X40N]
R85  4.7K  [RESC1005X40N]
R86  27K  [RESC1005X40N]
R87  4.7K  [RESC1005X40N]
R88  47K  [RESC1005X40N]
R89  15.0k  [RESC1005X40N]
R90  47K  [RESC1005X40N]
U16  CM2020-01  [SOP50P640X120-38N]

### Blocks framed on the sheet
LVDS0: J19 R76
MIPI Display: J18 R77
Parallel Camera 0: J17
MIPI Camera: J20 R79-R84
Parallel Display 0: J21 R78
HDMI: C80-C86 D3 P1 R85-R90 U16

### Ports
CSI0_DAT12 (bidir, see 2), CSI0_DAT13 (bidir, see 2), CSI0_DAT14 (bidir, see 2), CSI0_DAT15 (bidir, see 2), CSI0_DAT16 (bidir, see 2), CSI0_DAT17 (bidir, see 2), CSI0_DAT18 (bidir, see 2), CSI0_DAT19 (bidir, see 2), CSI0_GPIO (bidir, see 2), CSI0_HSYNC (bidir, see 2), CSI0_I2C_SCL (bidir, see 10), CSI0_I2C_SDA (bidir, see 10), CSI0_MCLK (bidir, see 2), CSI0_PIXCLK (bidir, see 2), CSI0_RESET_N (bidir, see 2), CSI0_VSYNC (bidir, see 2), CSI_CLK0_N (bidir, see 2), CSI_CLK0_P (bidir, see 2), CSI_D0_N (bidir, see 2), CSI_D0_P (bidir, see 2), CSI_D1_N (bidir, see 2), CSI_D1_P (bidir, see 2), CSI_D2_N (bidir, see 2), CSI_D2_P (bidir, see 2), CSI_D3_N (bidir, see 2), CSI_D3_P (bidir, see 2), CSI_I2C_SCL (bidir, see 10), CSI_I2C_SDA (bidir, see 10), CSI_RESET_N (bidir, see 2), DISP0_CLK (bidir, see 2), DISP0_CONTRAST (bidir, see 2), DISP0_DAT0 (bidir, see 2), DISP0_DAT1 (bidir, see 2), DISP0_DAT2 (bidir, see 2), DISP0_DAT3 (bidir, see 2), DISP0_DAT4 (bidir, see 2), DISP0_DAT5 (bidir, see 2), DISP0_DAT6 (bidir, see 2), DISP0_DAT7 (bidir, see 2), DISP0_DAT8 (bidir, see 2), DISP0_DAT9 (bidir, see 2), DISP0_DAT10 (bidir, see 2), DISP0_DAT11 (bidir, see 2), DISP0_DAT12 (bidir, see 2), DISP0_DAT13 (bidir, see 2), DISP0_DAT14 (bidir, see 2), DISP0_DAT15 (bidir, see 2), DISP0_DAT16 (bidir, see 2), DISP0_DAT17 (bidir, see 2), DISP0_DAT18 (bidir, see 2), DISP0_DAT19 (bidir, see 2), DISP0_DAT20 (bidir, see 2), DISP0_DAT21 (bidir, see 2), DISP0_DAT22 (bidir, see 2), DISP0_DAT23 (bidir, see 2), DISP0_DRDY (bidir, see 2), DISP0_HSYNC (bidir, see 2), DISP0_I2C_SCL (bidir, see 10), DISP0_I2C_SDA (bidir, see 10), DISP0_IRQ_N (bidir, see 2), DISP0_VSYNC (bidir, see 2), DSI_CLK0_N (bidir, see 2), DSI_CLK0_P (bidir, see 2), DSI_CONTRAST (bidir, see 2), DSI_D0_N (bidir, see 2), DSI_D0_P (bidir, see 2), DSI_D1_N (bidir, see 2), DSI_D1_P (bidir, see 2), DSI_I2C_SCL (bidir, see 10), DSI_I2C_SDA (bidir, see 10), DSI_IRQ_N (bidir, see 2), DSI_PWR_EN (bidir, see 2), DSI_RESET_N (bidir, see 2), HDMI_CEC_IN (bidir, see 2), HDMI_CLK_N (bidir, see 2), HDMI_CLK_P (bidir, see 2), HDMI_D0_N (bidir, see 2), HDMI_D0_P (bidir, see 2), HDMI_D1_N (bidir, see 2), HDMI_D1_P (bidir, see 2), HDMI_D2_N (bidir, see 2), HDMI_D2_P (bidir, see 2), HDMI_HPD (bidir, see 2), HDMI_I2C_SCL (bidir, see 10), HDMI_I2C_SDA (bidir, see 10), LVDS0_CLK_N (bidir, see 2), LVDS0_CLK_P (bidir, see 2), LVDS0_CONTRAST (bidir, see 2), LVDS0_I2C_SCL (bidir, see 10), LVDS0_I2C_SDA (bidir, see 10), LVDS0_IRQ_N (bidir, see 2), LVDS0_TX0_N (bidir, see 2), LVDS0_TX0_P (bidir, see 2), LVDS0_TX1_N (bidir, see 2), LVDS0_TX1_P (bidir, see 2), LVDS0_TX2_N (bidir, see 2), LVDS0_TX2_P (bidir, see 2), LVDS0_TX3_N (bidir, see 2), LVDS0_TX3_P (bidir, see 2)

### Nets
3V3: C82.2 D3.A J17.20 J18.1 J18.2 J19.1 J21.37 J21.38 R76.1 R77.1 R78.1 R88.1 R90.1 U16.2(LV_SUPPLY)
5V: C80.2 C81.2 J18.19 J18.20 J19.20 J20.21 J20.22 J20.23 J20.24 J21.39 J21.40 U16.1(5V_SUPPLY)
GND: C80.1 C81.1 C82.1 C83.1 C84.1 C85.1 C86.1 J17.1 J17.10 J17.17 J18.5 J18.8 J18.11 J18.16 J19.4 J19.7 J19.10 J19.13 J20.1 J20.9 J20.10 J20.13 J20.16 J20.19 J20.20 J21.1 J21.26 J21.28 J21.36 P1.2 P1.5 P1.8 P1.11 P1.17 R83.1 R84.1 R89.1 U16.3(GND) U16.5(TMDS_GND) U16.8(TMDS_GND) U16.11(TMDS_GND) U16.14(TMDS_GND) U16.25(TMDS_GND) U16.28(TMDS_GND) U16.31(TMDS_GND) U16.34(TMDS_GND) U16.36(GND)
SHLD: P1.M1 P1.M2 P1.M3 P1.M4
CSI0_DAT12: J17.2 ; port CSI0_DAT12
CSI0_DAT13: J17.3 ; port CSI0_DAT13
CSI0_DAT14: J17.4 ; port CSI0_DAT14
CSI0_DAT15: J17.5 ; port CSI0_DAT15
CSI0_DAT16: J17.6 ; port CSI0_DAT16
CSI0_DAT17: J17.7 ; port CSI0_DAT17
CSI0_DAT18: J17.8 ; port CSI0_DAT18
CSI0_DAT19: J17.9 ; port CSI0_DAT19
CSI0_GPIO: J17.15 ; port CSI0_GPIO
CSI0_HSYNC: J17.13 ; port CSI0_HSYNC
CSI0_I2C_SCL: J17.18 ; port CSI0_I2C_SCL
CSI0_I2C_SDA: J17.19 ; port CSI0_I2C_SDA
CSI0_MCLK: J17.11 ; port CSI0_MCLK
CSI0_PIXCLK: J17.12 ; port CSI0_PIXCLK
CSI0_RESET_N: J17.16 ; port CSI0_RESET_N
CSI0_VSYNC: J17.14 ; port CSI0_VSYNC
CSI_CLK0_N: J20.15 ; port CSI_CLK0_N
CSI_CLK0_P: J20.14 ; port CSI_CLK0_P
CSI_D0_N: J20.12 ; port CSI_D0_N
CSI_D0_P: J20.11 ; port CSI_D0_P
CSI_D1_N: J20.18 ; port CSI_D1_N
CSI_D1_P: J20.17 ; port CSI_D1_P
CSI_D2_N: R82.1 ; port CSI_D2_N
CSI_D2_P: R81.1 ; port CSI_D2_P
CSI_D3_N: R80.1 ; port CSI_D3_N
CSI_D3_P: R79.1 ; port CSI_D3_P
CSI_I2C_SCL: J20.2 ; port CSI_I2C_SCL
CSI_I2C_SDA: J20.3 ; port CSI_I2C_SDA
CSI_RESET_N: J20.4 ; port CSI_RESET_N
CSID2_N: J20.8 R82.2
CSID2_P: J20.7 R81.2
CSID3_N: J20.6 R80.2 R83.2
CSID3_P: J20.5 R79.2 R84.2
DISP0_CLK: J21.27 ; port DISP0_CLK
DISP0_CONTRAST: J21.32 ; port DISP0_CONTRAST
DISP0_DAT0: J21.2 ; port DISP0_DAT0
DISP0_DAT1: J21.3 ; port DISP0_DAT1
DISP0_DAT2: J21.4 ; port DISP0_DAT2
DISP0_DAT3: J21.5 ; port DISP0_DAT3
DISP0_DAT4: J21.6 ; port DISP0_DAT4
DISP0_DAT5: J21.7 ; port DISP0_DAT5
DISP0_DAT6: J21.8 ; port DISP0_DAT6
DISP0_DAT7: J21.9 ; port DISP0_DAT7
DISP0_DAT8: J21.10 ; port DISP0_DAT8
DISP0_DAT9: J21.11 ; port DISP0_DAT9
DISP0_DAT10: J21.12 ; port DISP0_DAT10
DISP0_DAT11: J21.13 ; port DISP0_DAT11
DISP0_DAT12: J21.14 ; port DISP0_DAT12
DISP0_DAT13: J21.15 ; port DISP0_DAT13
DISP0_DAT14: J21.16 ; port DISP0_DAT14
DISP0_DAT15: J21.17 ; port DISP0_DAT15
DISP0_DAT16: J21.18 ; port DISP0_DAT16
DISP0_DAT17: J21.19 ; port DISP0_DAT17
DISP0_DAT18: J21.20 ; port DISP0_DAT18
DISP0_DAT19: J21.21 ; port DISP0_DAT19
DISP0_DAT20: J21.22 ; port DISP0_DAT20
DISP0_DAT21: J21.23 ; port DISP0_DAT21
DISP0_DAT22: J21.24 ; port DISP0_DAT22
DISP0_DAT23: J21.25 ; port DISP0_DAT23
DISP0_DRDY: J21.31 ; port DISP0_DRDY
DISP0_HSYNC: J21.29 ; port DISP0_HSYNC
DISP0_I2C_SCL: J21.33 ; port DISP0_I2C_SCL
DISP0_I2C_SDA: J21.34 ; port DISP0_I2C_SDA
DISP0_IRQ_N: J21.35 R78.2 ; port DISP0_IRQ_N
DISP0_VSYNC: J21.30 ; port DISP0_VSYNC
DSI_CLK0_N: J18.7 ; port DSI_CLK0_N
DSI_CLK0_P: J18.6 ; port DSI_CLK0_P
DSI_CONTRAST: J18.13 ; port DSI_CONTRAST
DSI_D0_N: J18.4 ; port DSI_D0_N
DSI_D0_P: J18.3 ; port DSI_D0_P
DSI_D1_N: J18.10 ; port DSI_D1_N
DSI_D1_P: J18.9 ; port DSI_D1_P
DSI_I2C_SCL: J18.17 ; port DSI_I2C_SCL
DSI_I2C_SDA: J18.18 ; port DSI_I2C_SDA
DSI_IRQ_N: J18.12 R77.2 ; port DSI_IRQ_N
DSI_PWR_EN: J18.15 ; port DSI_PWR_EN
DSI_RESET_N: J18.14 ; port DSI_RESET_N
HDMI_CEC_IN: R88.2 U16.16(CE_REMOTE_IN) ; port HDMI_CEC_IN
HDMI_CLK_N: P1.12 U16.15(TMDS_CK-) U16.24(TMDS_CK-) ; port HDMI_CLK_N
HDMI_CLK_P: P1.10 U16.13(TMDS_CK+) U16.26(TMDS_CK+) ; port HDMI_CLK_P
HDMI_D0_N: P1.9 U16.12(TMDS_D0-) U16.27(TMDS_D0-) ; port HDMI_D0_N
HDMI_D0_P: P1.7 U16.10(TMDS_D0+) U16.29(TMDS_D0+) ; port HDMI_D0_P
HDMI_D1_N: P1.6 U16.9(TMDS_D1-) U16.30(TMDS_D1-) ; port HDMI_D1_N
HDMI_D1_P: P1.4 U16.7(TMDS_D1+) U16.32(TMDS_D1+) ; port HDMI_D1_P
HDMI_D2_N: P1.3 U16.6(TMDS_D2-) U16.33(TMDS_D2-) ; port HDMI_D2_N
HDMI_D2_P: P1.1 U16.4(TMDS_D2+) U16.35(TMDS_D2+) ; port HDMI_D2_P
HDMI_DDC_SCL: P1.15 R87.1 U16.22(DDC_CLK_OUT)
HDMI_DDC_SDA: P1.16 R85.1 U16.21(DDC_DAT_OUT)
HDMI_HPD: C83.2 R90.2 U16.19(HOTPLUG_DET_IN) ; port HDMI_HPD
HDMI_I2C_SCL: U16.17(DDC_CLK_IN) ; port HDMI_I2C_SCL
HDMI_I2C_SDA: U16.18(DDC_DAT_IN) ; port HDMI_I2C_SDA
HDMICEC: P1.13 R86.2 U16.23(CE_REMOTE_OUT)
HDMIHPD: C85.2 P1.19 R89.2 U16.20(HOTPLUG_DET_OUT)
LVDS0_CLK_N: J19.11 ; port LVDS0_CLK_N
LVDS0_CLK_P: J19.12 ; port LVDS0_CLK_P
LVDS0_CONTRAST: J19.16 ; port LVDS0_CONTRAST
LVDS0_I2C_SCL: J19.17 ; port LVDS0_I2C_SCL
LVDS0_I2C_SDA: J19.18 ; port LVDS0_I2C_SDA
LVDS0_IRQ_N: J19.19 R76.2 ; port LVDS0_IRQ_N
LVDS0_TX0_N: J19.2 ; port LVDS0_TX0_N
LVDS0_TX0_P: J19.3 ; port LVDS0_TX0_P
LVDS0_TX1_N: J19.5 ; port LVDS0_TX1_N
LVDS0_TX1_P: J19.6 ; port LVDS0_TX1_P
LVDS0_TX2_N: J19.8 ; port LVDS0_TX2_N
LVDS0_TX2_P: J19.9 ; port LVDS0_TX2_P
LVDS0_TX3_N: J19.14 ; port LVDS0_TX3_N
LVDS0_TX3_P: J19.15 ; port LVDS0_TX3_P
NetC84_2: C84.2 U16.37(ESD_BYP)
NetC86_2: C86.2 P1.18 R85.2 R87.2 U16.38(5V_OUT)
NetD3_K: D3.K R86.1

Not connected (* = marked no-connect by the designer): P1 14*

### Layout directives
differential pair; net class DIFF100: CSID2_N, CSID2_P, CSID3_N, CSID3_P

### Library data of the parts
C80 = 1000500: as C40 on sheet 06 - Gigabit Ethernet, Mini PCIe, microSIM
C81-C86 = 1000006: as C29 on sheet 06 - Gigabit Ethernet, Mini PCIe, microSIM
D3 = 1001169: DIODE SCHOTTKY 30V 0.2A SOT23-3; Part_Type: IC; Manufacturer: Fairchild Semiconductor; Digi_PN: 17050507; Component_Life_Cycle_State: Reviewed; Area: 8; Project: CCWMX6_SBC board
J17 J18 = 1001145: CONN FPC 20POS 0.5MM PITCH SMD; Part_Type: Connector; Manufacturer: Omron; Digi_PN: 18000675; Component_Life_Cycle_State: Reviewed; Area: 69.09; Project: CCWMX6_SBC board
J19 = 1001132: CONN HEADER 20POS 1.25MM R/A SMD; Part_Type: Connector; Manufacturer: Hirose; Digi_PN: 18050231; Component_Life_Cycle_State: Reviewed; Area: 206.34; Project: CCWMX6_SBC board
J20 = 1001182: CONN FPC 24POS 0.5MM PITCH SMD; Part_Type: Connector; Manufacturer: Omron; Digi_PN: 18000681; Component_Life_Cycle_State: Reviewed; Area: 69; Project: CCWMX6_SBC board
J21 = 1001144: CONN FPC 40POS 0.5MM PITCH SMD; Part_Type: Connector; Manufacturer: Omron; Digi_PN: 18000676; Component_Life_Cycle_State: Reviewed; Area: 117.5; Project: CCWMX6_SBC board
P1 = 1001123: HDMI RECEPTACLE, SMT; Part_Type: Connector; Manufacturer: KYCON; Digi_PN: 18000451; Component_Life_Cycle_State: Reviewed; Area: 174; Project: CCWMX6_SBC board
R76-R78 = 1000537: as R53 on sheet 06 - Gigabit Ethernet, Mini PCIe, microSIM
R79-R84 = 1000076: as R44 on sheet 06 - Gigabit Ethernet, Mini PCIe, microSIM
R85 R87 = 1000038: as R40 on sheet 06 - Gigabit Ethernet, Mini PCIe, microSIM
R86 = 1001153: RES 27.0K OHM 1/16W 1% 0402 SMD; Part_Type: Resistor; Manufacturer: Yageo; Manufacturer_Part_Number: RC0402FR-0727KL; Digi_PN: 13050609; Component_Life_Cycle_State: Reviewed; Area: 0.95; Project: CCWMX6_SBC board
R88 R90 = 1001155: as R68 on sheet 07 - USB OTG, USB HUB, USB Host
R89 = 1000174: RES 15.0K OHM 1/10W 1% 0402 SMD; Part_Type: Resistor; Manufacturer: Panasonic - ECG; Manufacturer_Part_Number: ERJ-2RKF1502X; Component_Life_Cycle_State: CAD Reviewed; Area: 0.95; Project: KITT; Power_WV_SRF: 10; Digi_PN: 13050446
U16 = 1001125: IC HDMI XMITTER PORT P/I 38TSSOP; Manufacturer: On Semiconductor; Digi_PN: 16051861; Component_Life_Cycle_State: Reviewed; Area: 43; Project: CCWMX6_SBC board

## Sheet 09 - Audio.SchDoc: Audio
size A3; PageSetup: Record=PageOptions|CenterHorizontal=True|CenterVertical=True|PrintScale=0.70|XCorrection=1.00|YCorrection=1.00|PrintKind=0|BorderSize=5000000|LeftOffset=0|BottomOffset=0|Orientation=2|PaperLength=4200|PaperWidth=2970|Scale=100|PaperSource=7|PrintQuality=600|MediaType=1|DitherType=10|PaperKind=A4|PrintScaleMode=1; Author: Daniel Alesanco; SheetNumber: 9; SheetTotal: 13
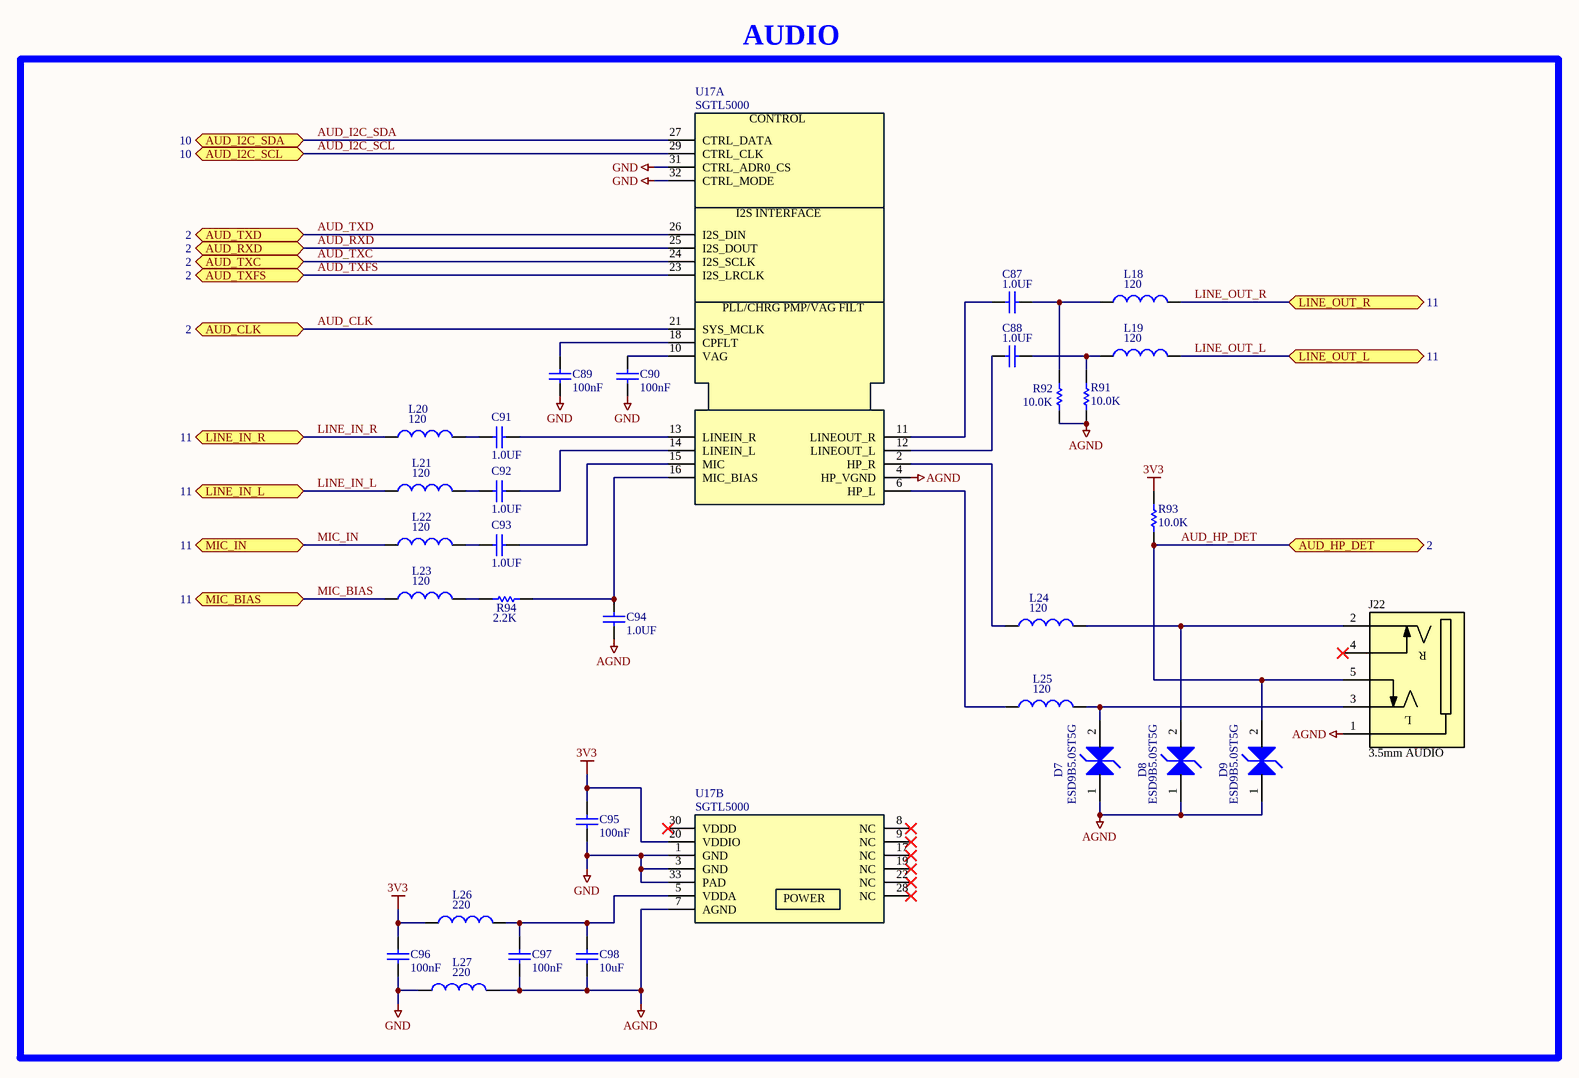
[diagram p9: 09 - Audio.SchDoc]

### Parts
C87  1.0UF  [CAPC1005X55N]
C88  1.0UF  [CAPC1005X55N]
C89  100nF  [CAPC1005X55N]
C90  100nF  [CAPC1005X55N]
C91  1.0UF  [CAPC1005X55N]
C92  1.0UF  [CAPC1005X55N]
C93  1.0UF  [CAPC1005X55N]
C94  1.0UF  [CAPC1005X55N]
C95  100nF  [CAPC1005X55N]
C96  100nF  [CAPC1005X55N]
C97  100nF  [CAPC1005X55N]
C98  10uF  [CAPC1005X55N]
D7  ESD9B5.0ST5G  [SODFL1006X43N12]
D8  ESD9B5.0ST5G  [SODFL1006X43N12]
D9  ESD9B5.0ST5G  [SODFL1006X43N12]
J22  3.5mm AUDIO  [CUI_SJ1-3515-SMT]
L18  120  [INDC1005X60N]
L19  120  [INDC1005X60N]
L20  120  [INDC1005X60N]
L21  120  [INDC1005X60N]
L22  120  [INDC1005X60N]
L23  120  [INDC1005X60N]
L24  120  [INDC1005X60N]
L25  120  [INDC1005X60N]
L26  220  [INDC2013X110N]
L27  220  [INDC2013X110N]
R91  10.0K  [RESC1005X40N]
R92  10.0K  [RESC1005X40N]
R93  10.0K  [RESC1005X40N]
R94  2.2K  [RESC1005X40N]
U17  SGTL5000  [QFN50P500X500X100-33CN]  (parts A,B of 2)

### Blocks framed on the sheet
AUDIO: C87-C98 D7-D9 J22 L18-L27 R91-R94 U17

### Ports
AUD_CLK (bidir, see 2), AUD_HP_DET (bidir, see 2), AUD_I2C_SCL (bidir, see 10), AUD_I2C_SDA (bidir, see 10), AUD_RXD (bidir, see 2), AUD_TXC (bidir, see 2), AUD_TXD (bidir, see 2), AUD_TXFS (bidir, see 2), LINE_IN_L (bidir, see 11), LINE_IN_R (bidir, see 11), LINE_OUT_L (bidir, see 11), LINE_OUT_R (bidir, see 11), MIC_BIAS (bidir, see 11), MIC_IN (bidir, see 11)

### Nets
3V3: C95.2 C96.2 L26.1 R93.2 U17.20(VDDIO)
AGND: C94.1 C97.1 C98.1 D7.1 D8.1 D9.1 J22.1 L27.2 R91.1 R92.1 U17.4(HP_VGND) U17.7(AGND)
GND: C89.1 C90.1 C95.1 C96.1 L27.1 U17.1(GND) U17.3(GND) U17.31(CTRL_ADR0_CS) U17.32(CTRL_MODE) U17.33(PAD)
AUD_CLK: U17.21(SYS_MCLK) ; port AUD_CLK
AUD_HP_DET: D9.2 J22.5 R93.1 ; port AUD_HP_DET
AUD_I2C_SCL: U17.29(CTRL_CLK) ; port AUD_I2C_SCL
AUD_I2C_SDA: U17.27(CTRL_DATA) ; port AUD_I2C_SDA
AUD_RXD: U17.25(I2S_DOUT) ; port AUD_RXD
AUD_TXC: U17.24(I2S_SCLK) ; port AUD_TXC
AUD_TXD: U17.26(I2S_DIN) ; port AUD_TXD
AUD_TXFS: U17.23(I2S_LRCLK) ; port AUD_TXFS
LINE_IN_L: L21.1 ; port LINE_IN_L
LINE_IN_R: L20.1 ; port LINE_IN_R
LINE_OUT_L: L19.2 ; port LINE_OUT_L
LINE_OUT_R: L18.2 ; port LINE_OUT_R
MIC_BIAS: L23.1 ; port MIC_BIAS
MIC_IN: L22.1 ; port MIC_IN
NetC87_1: C87.1 U17.11(LINEOUT_R)
NetC87_2: C87.2 L18.1 R92.2
NetC88_1: C88.1 U17.12(LINEOUT_L)
NetC88_2: C88.2 L19.1 R91.2
NetC89_2: C89.2 U17.18(CPFLT)
NetC90_2: C90.2 U17.10(VAG)
NetC91_1: C91.1 L20.2
NetC91_2: C91.2 U17.13(LINEIN_R)
NetC92_1: C92.1 L21.2
NetC92_2: C92.2 U17.14(LINEIN_L)
NetC93_1: C93.1 L22.2
NetC93_2: C93.2 U17.15(MIC)
NetC94_2: C94.2 R94.2 U17.16(MIC_BIAS)
NetC97_2: C97.2 C98.2 L26.2 U17.5(VDDA)
NetD7_2: D7.2 J22.3 L25.2
NetD8_2: D8.2 J22.2 L24.2
NetL23_2: L23.2 R94.1
NetL24_1: L24.1 U17.2(HP_R)
NetL25_1: L25.1 U17.6(HP_L)

Not connected (* = marked no-connect by the designer): J22 4*; U17 8(NC)* 9(NC)* 17(NC)* 19(NC)* 22(NC)* 28(NC)* 30(VDDD)*

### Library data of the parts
C87 C88 C91-C94 = 1001167: as C62 on sheet 07 - USB OTG, USB HUB, USB Host
C89 C90 C95-C97 = 1000006: as C29 on sheet 06 - Gigabit Ethernet, Mini PCIe, microSIM
C98 = 1001168: as C42 on sheet 06 - Gigabit Ethernet, Mini PCIe, microSIM
D7-D9 = 1001264: as D10 on sheet 07 - USB OTG, USB HUB, USB Host
J22 = 1001133: CONN JACK STEREO 5POS 3.5MM SMD; Part_Type: Connector; Manufacturer: CUI Inc.; Manufacturer_Part_Number: SJ1-3515-SMT; Digi_PN: MA02822; Component_Life_Cycle_State: Reviewed; Area: 114; Project: CCWMX6_SBC board
L18-L25 = 1001175: as L2 on sheet 06 - Gigabit Ethernet, Mini PCIe, microSIM
L26 L27 = 1001174: as L6 on sheet 07 - USB OTG, USB HUB, USB Host
R91-R93 = 1000537: as R53 on sheet 06 - Gigabit Ethernet, Mini PCIe, microSIM
R94 = 1001156: RES 2.20K OHM 1/16W 1% 0402 SMD; Part_Type: Resistor; Manufacturer: Yageo; Manufacturer_Part_Number: RC0402FR-072K2L; Digi_PN: 13050699; Component_Life_Cycle_State: Reviewed; Area: 0.95; Project: CCWMX6_SBC board
U17 = 1001126: IC AUDIO CODEC STEREO 32-QFN; Manufacturer: Freescale Semiconductor; Digi_PN: 16051534; Component_Life_Cycle_State: Reviewed; Area: 25; Project: CCWMX6_SBC board

## Sheet 10 - CAN, I2C, XBee.SchDoc: CAN, I2C, XBee
size A3; PageSetup: Record=PageOptions|CenterHorizontal=True|CenterVertical=True|PrintScale=0.70|XCorrection=1.00|YCorrection=1.00|PrintKind=0|BorderSize=5000000|LeftOffset=0|BottomOffset=0|Orientation=2|PaperLength=4200|PaperWidth=2970|Scale=100|PaperSource=7|PrintQuality=600|MediaType=1|DitherType=10|PaperKind=A4|PrintScaleMode=1; Author: Daniel Alesanco; SheetNumber: 10; SheetTotal: 13
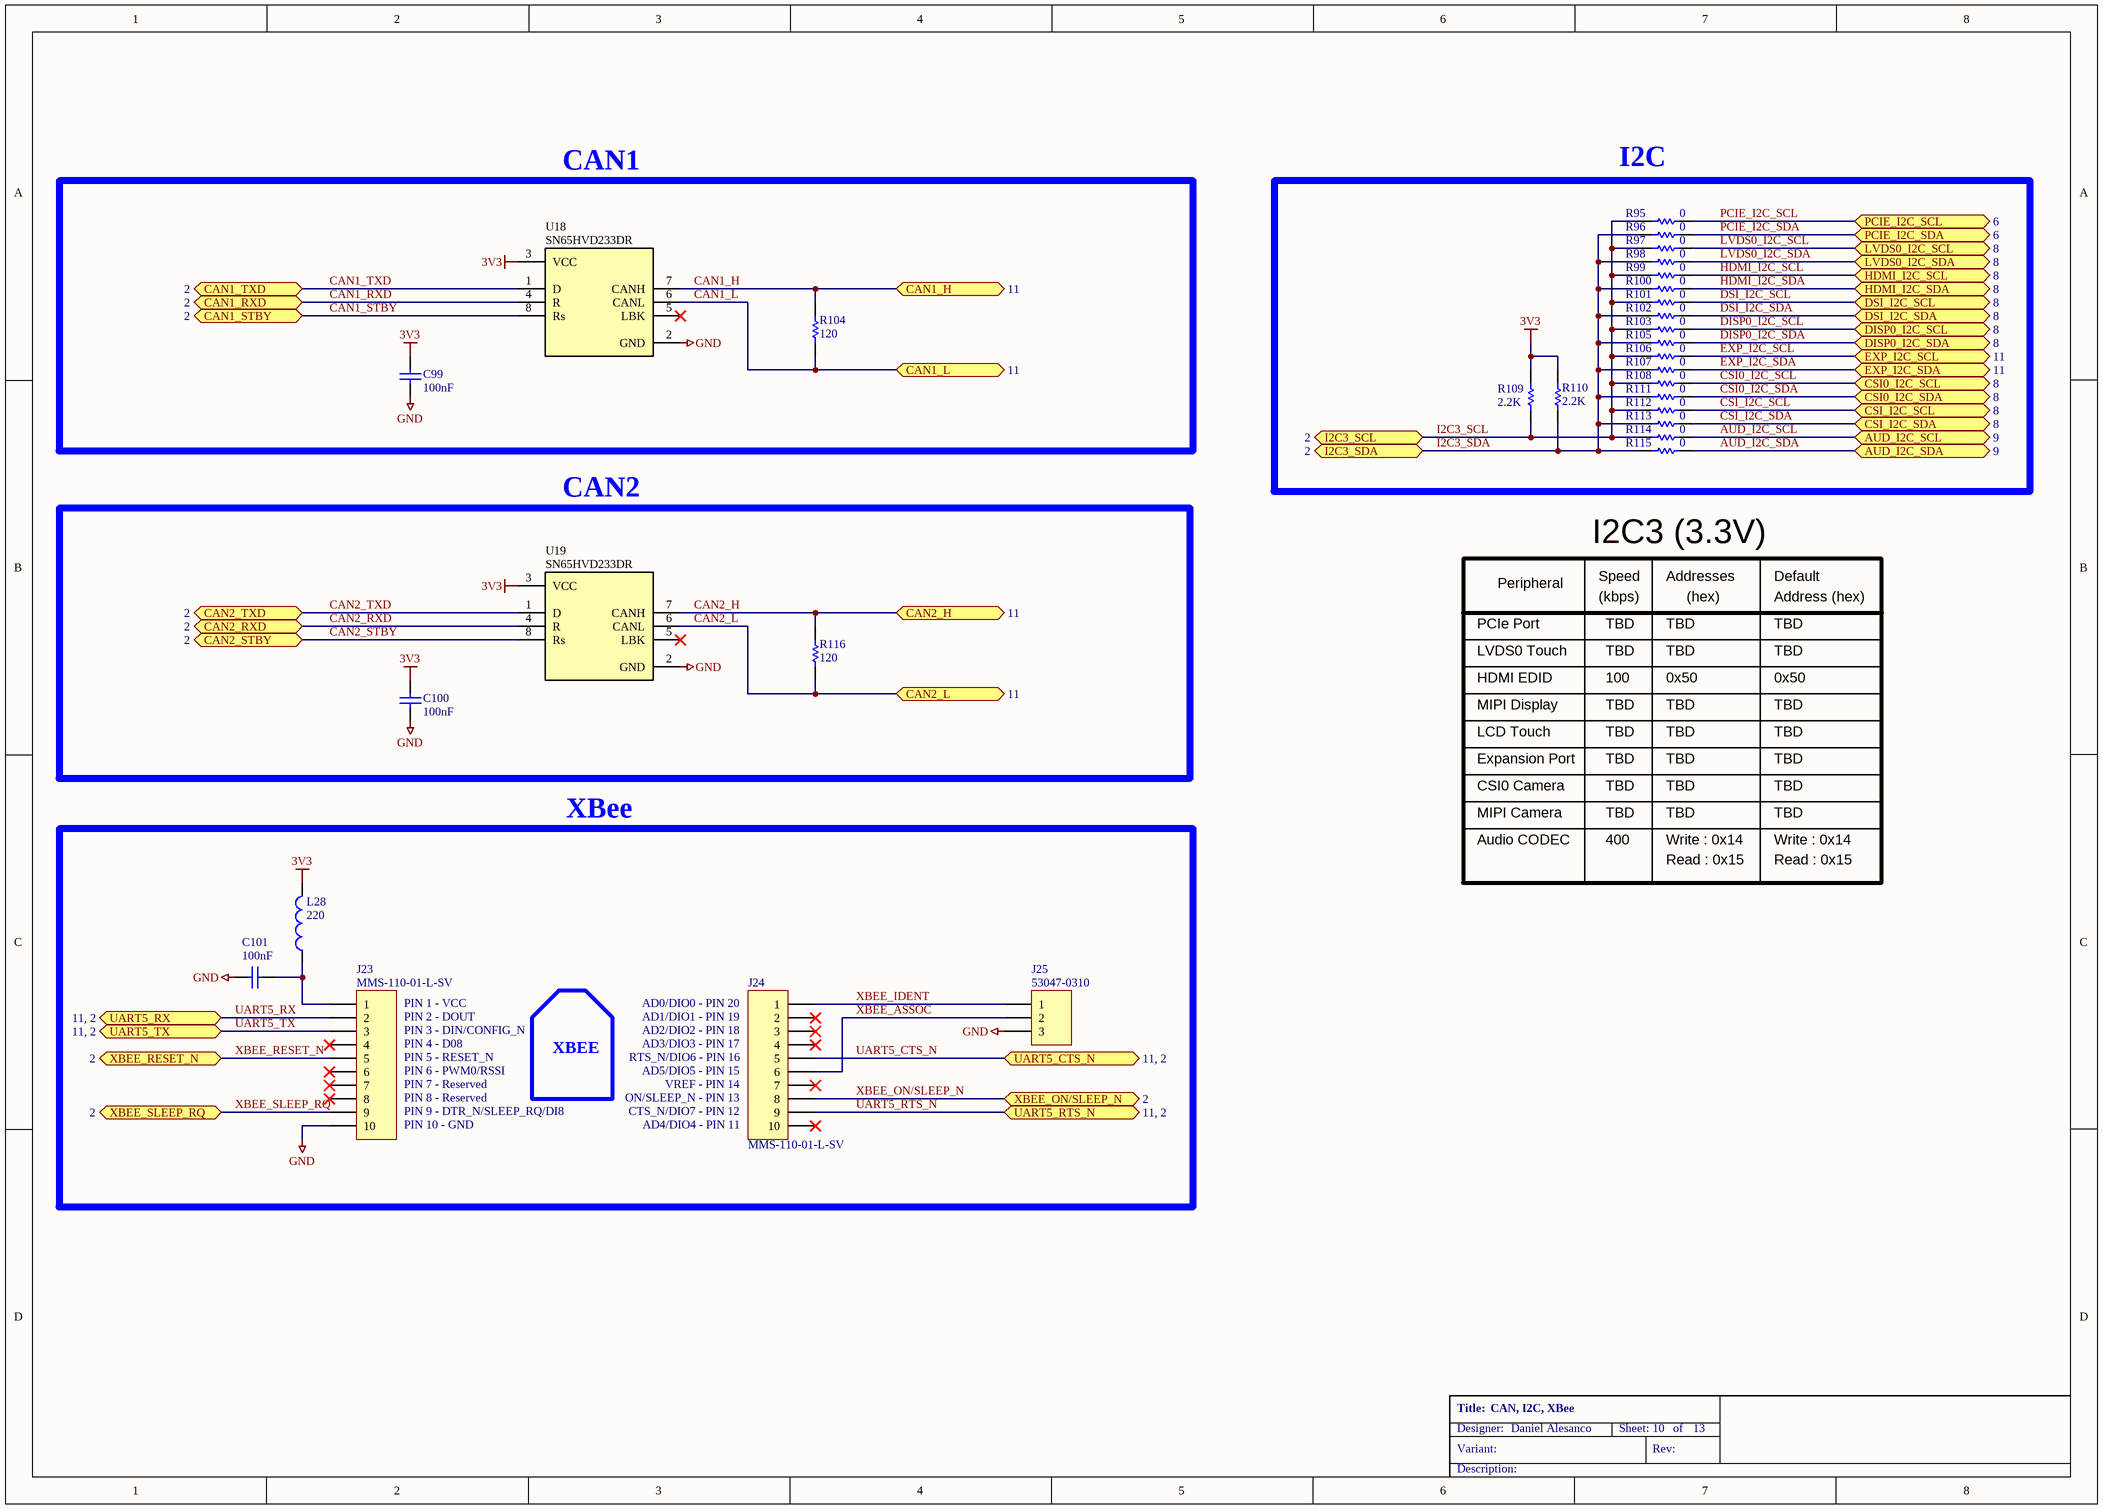
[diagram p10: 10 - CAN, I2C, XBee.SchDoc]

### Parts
C99  100nF  [CAPC1005X55N]
C100  100nF  [CAPC1005X55N]
C101  100nF  [CAPC1005X55N]
J23  Manufacturer_Part_Number: MMS-110-01-L-SV  [SAMTEC_MMS-110-01-L-SV]  (hidden comment: 1x10)
J24  Manufacturer_Part_Number: MMS-110-01-L-SV  [SAMTEC_MMS-110-01-L-SV]  (hidden comment: 1x10)
J25  Manufacturer_Part_Number: 53047-0310  [MOLEX_53047-0310]  (hidden comment: 1x3P)
L28  220  [INDC2013X110N]
R95  0  [RESC1005X40N]
R96  0  [RESC1005X40N]
R97  0  [RESC1005X40N]
R98  0  [RESC1005X40N]
R99  0  [RESC1005X40N]
R100  0  [RESC1005X40N]
R101  0  [RESC1005X40N]
R102  0  [RESC1005X40N]
R103  0  [RESC1005X40N]
R104  120  [RESC1005X40N]
R105  0  [RESC1005X40N]
R106  0  [RESC1005X40N]
R107  0  [RESC1005X40N]
R108  0  [RESC1005X40N]
R109  2.2K  [RESC1005X40N]
R110  2.2K  [RESC1005X40N]
R111  0  [RESC1005X40N]
R112  0  [RESC1005X40N]
R113  0  [RESC1005X40N]
R114  0  [RESC1005X40N]
R115  0  [RESC1005X40N]
R116  120  [RESC1005X40N]
U18  SN65HVD233DR  [SOIC127P600X175-8N]
U19  SN65HVD233DR  [SOIC127P600X175-8N]

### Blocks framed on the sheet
CAN1: C99 R104 U18
I2C: R95-R103 R105-R115
CAN2: C100 R116 U19
XBee: C101 J23-J25 L28

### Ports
AUD_I2C_SCL (bidir, see 9), AUD_I2C_SDA (bidir, see 9), CAN1_H (bidir, see 11), CAN1_L (bidir, see 11), CAN1_RXD (bidir, see 2), CAN1_STBY (bidir, see 2), CAN1_TXD (bidir, see 2), CAN2_H (bidir, see 11), CAN2_L (bidir, see 11), CAN2_RXD (bidir, see 2), CAN2_STBY (bidir, see 2), CAN2_TXD (bidir, see 2), CSI0_I2C_SCL (bidir, see 8), CSI0_I2C_SDA (bidir, see 8), CSI_I2C_SCL (bidir, see 8), CSI_I2C_SDA (bidir, see 8), DISP0_I2C_SCL (bidir, see 8), DISP0_I2C_SDA (bidir, see 8), DSI_I2C_SCL (bidir, see 8), DSI_I2C_SDA (bidir, see 8), EXP_I2C_SCL (bidir, see 11), EXP_I2C_SDA (bidir, see 11), HDMI_I2C_SCL (bidir, see 8), HDMI_I2C_SDA (bidir, see 8), I2C3_SCL (bidir, see 2), I2C3_SDA (bidir, see 2), LVDS0_I2C_SCL (bidir, see 8), LVDS0_I2C_SDA (bidir, see 8), PCIE_I2C_SCL (bidir, see 6), PCIE_I2C_SDA (bidir, see 6), UART5_CTS_N (bidir, see 11, 2), UART5_RTS_N (bidir, see 11, 2), UART5_RX (bidir, see 11, 2), UART5_TX (bidir, see 11, 2), XBEE_ON/SLEEP_N (bidir, see 2), XBEE_RESET_N (bidir, see 2), XBEE_SLEEP_RQ (bidir, see 2)

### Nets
3V3: C99.2 C100.2 L28.2 R109.2 R110.2 U18.3(VCC) U19.3(VCC)
GND: C99.1 C100.1 C101.1 J23.10 J25.3 U18.2(GND) U19.2(GND)
AUD_I2C_SCL: R114.2 ; port AUD_I2C_SCL
AUD_I2C_SDA: R115.2 ; port AUD_I2C_SDA
CAN1_H: R104.2 U18.7(CANH) ; port CAN1_H
CAN1_L: R104.1 U18.6(CANL) ; port CAN1_L
CAN1_RXD: U18.4(R) ; port CAN1_RXD
CAN1_STBY: U18.8(Rs) ; port CAN1_STBY
CAN1_TXD: U18.1(D) ; port CAN1_TXD
CAN2_H: R116.2 U19.7(CANH) ; port CAN2_H
CAN2_L: R116.1 U19.6(CANL) ; port CAN2_L
CAN2_RXD: U19.4(R) ; port CAN2_RXD
CAN2_STBY: U19.8(Rs) ; port CAN2_STBY
CAN2_TXD: U19.1(D) ; port CAN2_TXD
CSI0_I2C_SCL: R108.2 ; port CSI0_I2C_SCL
CSI0_I2C_SDA: R111.2 ; port CSI0_I2C_SDA
CSI_I2C_SCL: R112.2 ; port CSI_I2C_SCL
CSI_I2C_SDA: R113.2 ; port CSI_I2C_SDA
DISP0_I2C_SCL: R103.2 ; port DISP0_I2C_SCL
DISP0_I2C_SDA: R105.2 ; port DISP0_I2C_SDA
DSI_I2C_SCL: R101.2 ; port DSI_I2C_SCL
DSI_I2C_SDA: R102.2 ; port DSI_I2C_SDA
EXP_I2C_SCL: R106.2 ; port EXP_I2C_SCL
EXP_I2C_SDA: R107.2 ; port EXP_I2C_SDA
HDMI_I2C_SCL: R99.2 ; port HDMI_I2C_SCL
HDMI_I2C_SDA: R100.2 ; port HDMI_I2C_SDA
I2C3_SCL: R95.1 R97.1 R99.1 R101.1 R103.1 R106.1 R108.1 R109.1 R112.1 R114.1 ; port I2C3_SCL
I2C3_SDA: R96.1 R98.1 R100.1 R102.1 R105.1 R107.1 R110.1 R111.1 R113.1 R115.1 ; port I2C3_SDA
LVDS0_I2C_SCL: R97.2 ; port LVDS0_I2C_SCL
LVDS0_I2C_SDA: R98.2 ; port LVDS0_I2C_SDA
PCIE_I2C_SCL: R95.2 ; port PCIE_I2C_SCL
PCIE_I2C_SDA: R96.2 ; port PCIE_I2C_SDA
UART5_CTS_N: J24.5 ; port UART5_CTS_N
UART5_RTS_N: J24.9 ; port UART5_RTS_N
UART5_RX: J23.2 ; port UART5_RX
UART5_TX: J23.3 ; port UART5_TX
XBEE_ASSOC: J24.6 J25.2
XBEE_IDENT: J24.1 J25.1
XBEE_ON/SLEEP_N: J24.8 ; port XBEE_ON/SLEEP_N
XBEE_RESET_N: J23.5 ; port XBEE_RESET_N
XBEE_SLEEP_RQ: J23.9 ; port XBEE_SLEEP_RQ
NetC101_2: C101.2 J23.1 L28.1

Not connected (* = marked no-connect by the designer): J23 4* 6* 7* 8*; J24 2* 3* 4* 7* 10*; U18 5(LBK)*; U19 5(LBK)*

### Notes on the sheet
- Peripheral
- I2C3 (3.3V)
- Speed
- Addresses
- Default
- PCIe Port
- (kbps)
- TBD
- (hex)
- Address (hex)
- LVDS0 Touch
- HDMI EDID
- MIPI Display
- 100
- 0x50
- LCD Touch
- Expansion Port
- CSI0 Camera
- MIPI Camera
- Audio CODEC
- 400
- Write : 0x14
- Read : 0x15
- (near J23) PIN 1 - VCC
- (near J23) PIN 2 - DOUT
- (near J23) PIN 3 - DIN/CONFIG_N
- (near J23) PIN 4 - D08
- XBEE
- (near J24) AD0/DIO0 - PIN 20
- (near J24) AD1/DIO1 - PIN 19
- (near J24) AD2/DIO2 - PIN 18
- (near J24) AD3/DIO3 - PIN 17
- (near J23) PIN 5 - RESET_N
- (near J23) PIN 6 - PWM0/RSSI
- (near J23) PIN 7 - Reserved
- (near J23) PIN 8 - Reserved
- (near J23) PIN 9 - DTR_N/SLEEP_RQ/DI8
- (near J23) PIN 10 - GND
- (near J24) RTS_N/DIO6 - PIN 16
- (near J24) AD5/DIO5 - PIN 15
- (near J24) VREF - PIN 14
- (near J24) ON/SLEEP_N - PIN 13
- (near J24) CTS_N/DIO7 - PIN 12
- (near J24) AD4/DIO4 - PIN 11

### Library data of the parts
C99-C101 = 1000006: as C29 on sheet 06 - Gigabit Ethernet, Mini PCIe, microSIM
J23 J24 = 1001131: CONN RCPT 2MM 10POS SGL VERT PCB; Part_Type: Connector; Manufacturer: Samtec; Digi_PN: 18050108; Component_Life_Cycle_State: Reviewed; Area: 40; Project: CCWMX6_SBC board
J25 = 1001183: CONN HEADER 3POS 1.25MM VERT TIN; Part_Type: Connector; Manufacturer: Molex; Digi_PN: 18050349; Component_Life_Cycle_State: Reviewed; Area: 17.6; Project: CCWMX6_SBC board
L28 = 1001174: as L6 on sheet 07 - USB OTG, USB HUB, USB Host
R95-R103 R105-R108 R111-R115 = 1000076: as R44 on sheet 06 - Gigabit Ethernet, Mini PCIe, microSIM
R104 R116 = 1001158: RES 120 OHM 1/16W 1% 0402 SMD; Part_Type: Resistor; Manufacturer: Yageo; Manufacturer_Part_Number: RC0402FR-07120RL; Digi_PN: 13050832; Component_Life_Cycle_State: Reviewed; Area: 0.95; Project: CCWMX6_SBC board
R109 R110 = 1001156: as R94 on sheet 09 - Audio
U18 U19 = 1001129: IC CAN TRANSCEIVER 3.3V 8-SOIC; Manufacturer: Texas Instruments; Digi_PN: TA02540; Component_Life_Cycle_State: Reviewed; Area: 20; Project: CCWMX6_SBC board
